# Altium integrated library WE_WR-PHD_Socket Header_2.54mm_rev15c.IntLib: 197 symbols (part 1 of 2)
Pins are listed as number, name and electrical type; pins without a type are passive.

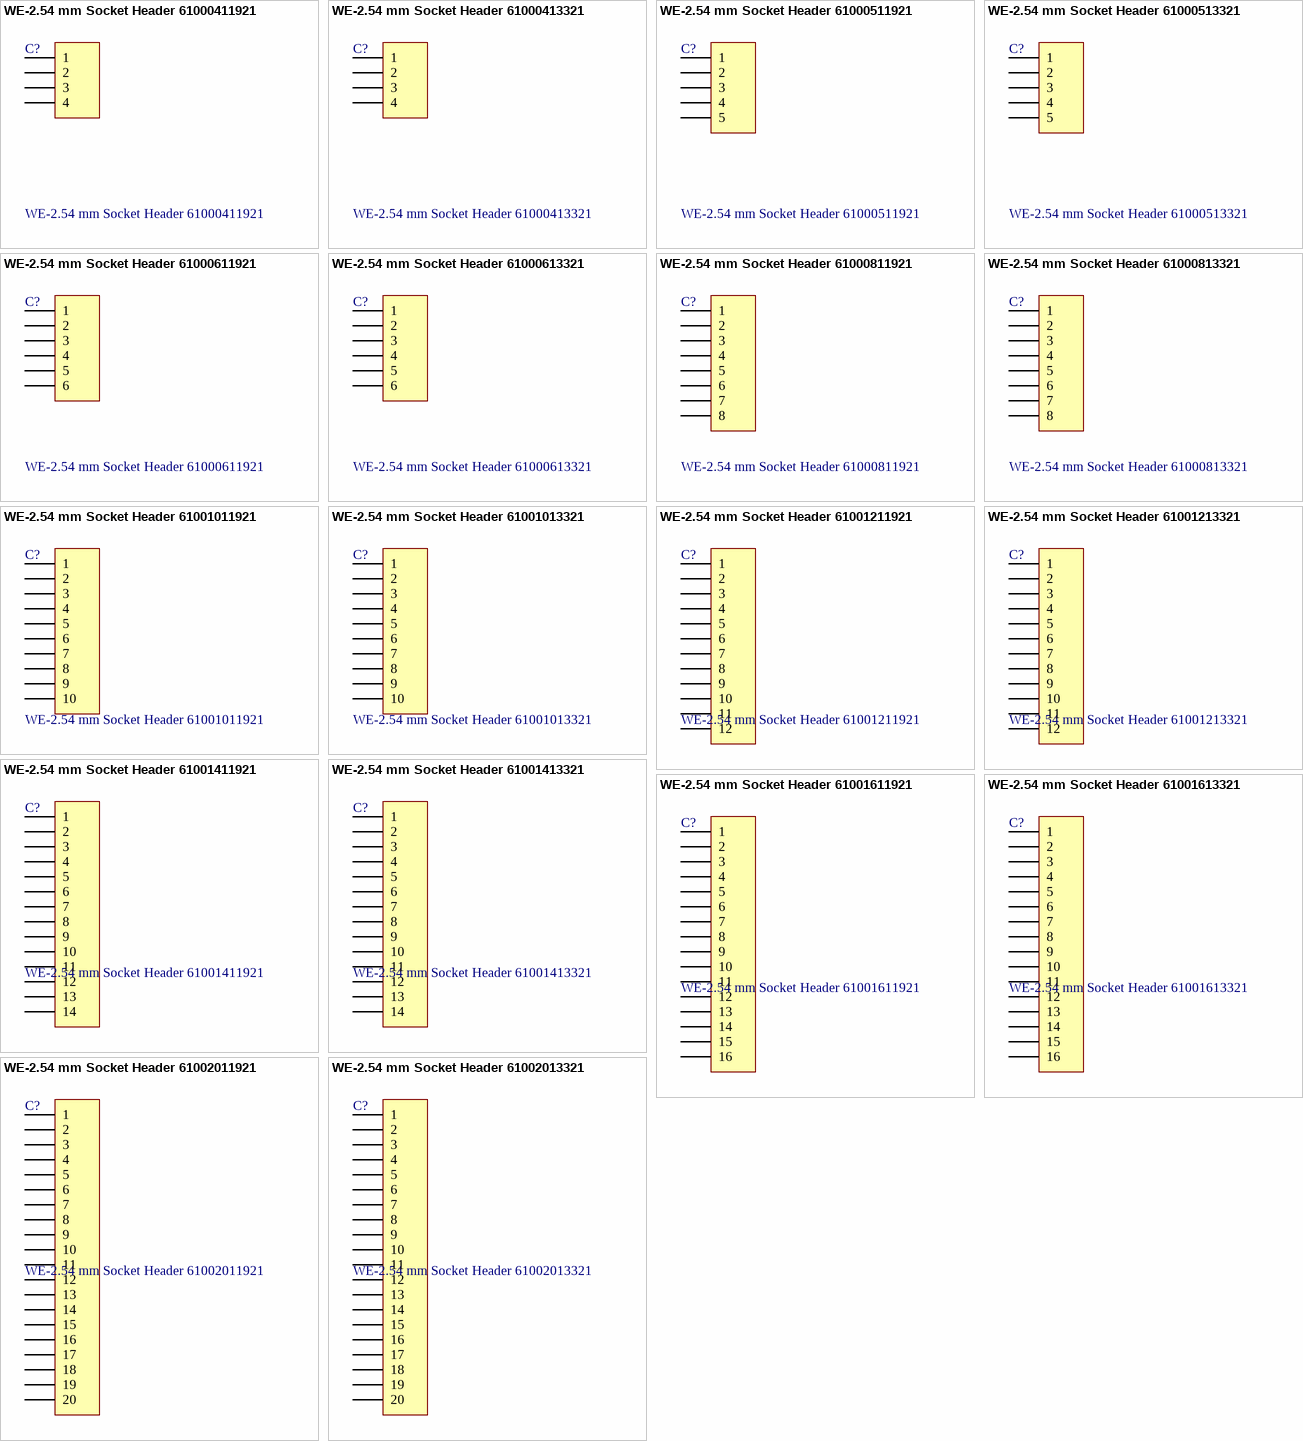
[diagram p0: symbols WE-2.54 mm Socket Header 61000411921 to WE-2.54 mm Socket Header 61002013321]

## WE-2.54 mm Socket Header 61000411921
designator C?
WR-PHD 2.54 mm SMT Socket Header; Manufacturer: Würth Elektronik eiSos GmbH; ComponentLink1 Description: Manufacturer; ComponentLink2 Description: Datasheet; NoPins: 4
footprint 61000411921 (4 pins, 1 row, straight, Type 1, gold plating)
pins: 1, 2, 3, 4

## WE-2.54 mm Socket Header 61000413321
designator C?
WR-PHD 2.54 mm SMT Socket Header; Manufacturer: Würth Elektronik eiSos GmbH; ComponentLink1 Description: Manufacturer; ComponentLink2 Description: Datasheet; NoPins: 4
footprint 61000413321 (4 pins, 1 row, straight, Type 2, gold plating)
pins: 1, 2, 3, 4

## WE-2.54 mm Socket Header 61000511921
designator C?
WR-PHD 2.54 mm SMT Socket Header; Manufacturer: Würth Elektronik eiSos GmbH; ComponentLink1 Description: Manufacturer; ComponentLink2 Description: Datasheet; NoPins: 5
footprint 61000511921 (5 pins, 1 row, straight, Type 1, gold plating)
pins: 1, 2, 3, 4, 5

## WE-2.54 mm Socket Header 61000513321
designator C?
WR-PHD 2.54 mm SMT Socket Header; Manufacturer: Würth Elektronik eiSos GmbH; ComponentLink1 Description: Manufacturer; ComponentLink2 Description: Datasheet; NoPins: 5
footprint 61000513321 (5 pins, 1 row, straight, Type 2, gold plating)
pins: 1, 2, 3, 4, 5

## WE-2.54 mm Socket Header 61000611921
designator C?
WR-PHD 2.54 mm SMT Socket Header; Manufacturer: Würth Elektronik eiSos GmbH; ComponentLink1 Description: Manufacturer; ComponentLink2 Description: Datasheet; NoPins: 6
footprint 61000611921 (6 pins, 1 row, straight, Type 1, gold plating)
pins: 1, 2, 3, 4, 5, 6

## WE-2.54 mm Socket Header 61000613321
designator C?
WR-PHD 2.54 mm SMT Socket Header; Manufacturer: Würth Elektronik eiSos GmbH; ComponentLink1 Description: Manufacturer; ComponentLink2 Description: Datasheet; NoPins: 6
footprint 61000613321 (6 pins, 1 row, straight, Type 2, gold plating)
pins: 1, 2, 3, 4, 5, 6

## WE-2.54 mm Socket Header 61000811921
designator C?
WR-PHD 2.54 mm SMT Socket Header; Manufacturer: Würth Elektronik eiSos GmbH; ComponentLink1 Description: Manufacturer; ComponentLink2 Description: Datasheet; NoPins: 8
footprint 61000811921 (8 pins, 1 row, straight, Type 1, gold plating)
pins: 1, 2, 3, 4, 5, 6, 7, 8

## WE-2.54 mm Socket Header 61000813321
designator C?
WR-PHD 2.54 mm SMT Socket Header; Manufacturer: Würth Elektronik eiSos GmbH; ComponentLink1 Description: Manufacturer; ComponentLink2 Description: Datasheet; NoPins: 8
footprint 61000813321 (8 pins, 1 row, straight, Type 2, gold plating)
pins: 1, 2, 3, 4, 5, 6, 7, 8

## WE-2.54 mm Socket Header 61001011921
designator C?
WR-PHD 2.54 mm SMT Socket Header; Manufacturer: Würth Elektronik eiSos GmbH; ComponentLink1 Description: Manufacturer; ComponentLink2 Description: Datasheet; NoPins: 10
footprint 61001011921 (10 pins, 1 row, straight, Type 1, gold plating)
pins: 1, 2, 3, 4, 5, 6, 7, 8, 9, 10

## WE-2.54 mm Socket Header 61001013321
designator C?
WR-PHD 2.54 mm SMT Socket Header; Manufacturer: Würth Elektronik eiSos GmbH; ComponentLink1 Description: Manufacturer; ComponentLink2 Description: Datasheet; NoPins: 10
footprint 61001013321 (10 pins, 1 row, straight, Type 2, gold plating)
pins: 1, 2, 3, 4, 5, 6, 7, 8, 9, 10

## WE-2.54 mm Socket Header 61001211921
designator C?
WR-PHD 2.54 mm SMT Socket Header; Manufacturer: Würth Elektronik eiSos GmbH; ComponentLink1 Description: Manufacturer; ComponentLink2 Description: Datasheet; NoPins: 12
footprint 61001211921 (12 pins, 1 row, straight, Type 1, gold plating)
pins: 1, 2, 3, 4, 5, 6, 7, 8, 9, 10, 11, 12

## WE-2.54 mm Socket Header 61001213321
designator C?
WR-PHD 2.54 mm SMT Socket Header; Manufacturer: Würth Elektronik eiSos GmbH; ComponentLink1 Description: Manufacturer; ComponentLink2 Description: Datasheet; NoPins: 12
footprint 61001213321 (12 pins, 1 row, straight, Type 2, gold plating)
pins: 1, 2, 3, 4, 5, 6, 7, 8, 9, 10, 11, 12

## WE-2.54 mm Socket Header 61001411921
designator C?
WR-PHD 2.54 mm SMT Socket Header; Manufacturer: Würth Elektronik eiSos GmbH; ComponentLink1 Description: Manufacturer; ComponentLink2 Description: Datasheet; NoPins: 14
footprint 61001411921 (14 pins, 1 row, straight, Type 1, gold plating)
pins: 1, 2, 3, 4, 5, 6, 7, 8, 9, 10, 11, 12, 13, 14

## WE-2.54 mm Socket Header 61001413321
designator C?
WR-PHD 2.54 mm SMT Socket Header; Manufacturer: Würth Elektronik eiSos GmbH; ComponentLink1 Description: Manufacturer; ComponentLink2 Description: Datasheet; NoPins: 14
footprint 61001413321 (14 pins, 1 row, straight, Type 2, gold plating)
pins: 1, 2, 3, 4, 5, 6, 7, 8, 9, 10, 11, 12, 13, 14

## WE-2.54 mm Socket Header 61001611921
designator C?
WR-PHD 2.54 mm SMT Socket Header; Manufacturer: Würth Elektronik eiSos GmbH; ComponentLink1 Description: Manufacturer; ComponentLink2 Description: Datasheet; NoPins: 16
footprint 61001611921 (16 pins, 1 row, straight, Type 1, gold plating)
pins: 1, 2, 3, 4, 5, 6, 7, 8, 9, 10, 11, 12, 13, 14, 15, 16

## WE-2.54 mm Socket Header 61001613321
designator C?
WR-PHD 2.54 mm SMT Socket Header; Manufacturer: Würth Elektronik eiSos GmbH; ComponentLink1 Description: Manufacturer; ComponentLink2 Description: Datasheet; NoPins: 16
footprint 61001613321 (16 pins, 1 row, straight, Type 2, gold plating)
pins: 1, 2, 3, 4, 5, 6, 7, 8, 9, 10, 11, 12, 13, 14, 15, 16

## WE-2.54 mm Socket Header 61002011921
designator C?
WR-PHD 2.54 mm SMT Socket Header; Manufacturer: Würth Elektronik eiSos GmbH; ComponentLink1 Description: Manufacturer; ComponentLink2 Description: Datasheet; NoPins: 20
footprint 61002011921 (20 pins, 1 row, straight, Type 1, gold plating)
pins: 1, 2, 3, 4, 5, 6, 7, 8, 9, 10, 11, 12, 13, 14, 15, 16, 17, 18, 19, 20

## WE-2.54 mm Socket Header 61002013321
designator C?
WR-PHD 2.54 mm SMT Socket Header; Manufacturer: Würth Elektronik eiSos GmbH; ComponentLink1 Description: Manufacturer; ComponentLink2 Description: Datasheet; NoPins: 20
footprint 61002013321 (20 pins, 1 row, straight, Type 2, gold plating)
pins: 1, 2, 3, 4, 5, 6, 7, 8, 9, 10, 11, 12, 13, 14, 15, 16, 17, 18, 19, 20


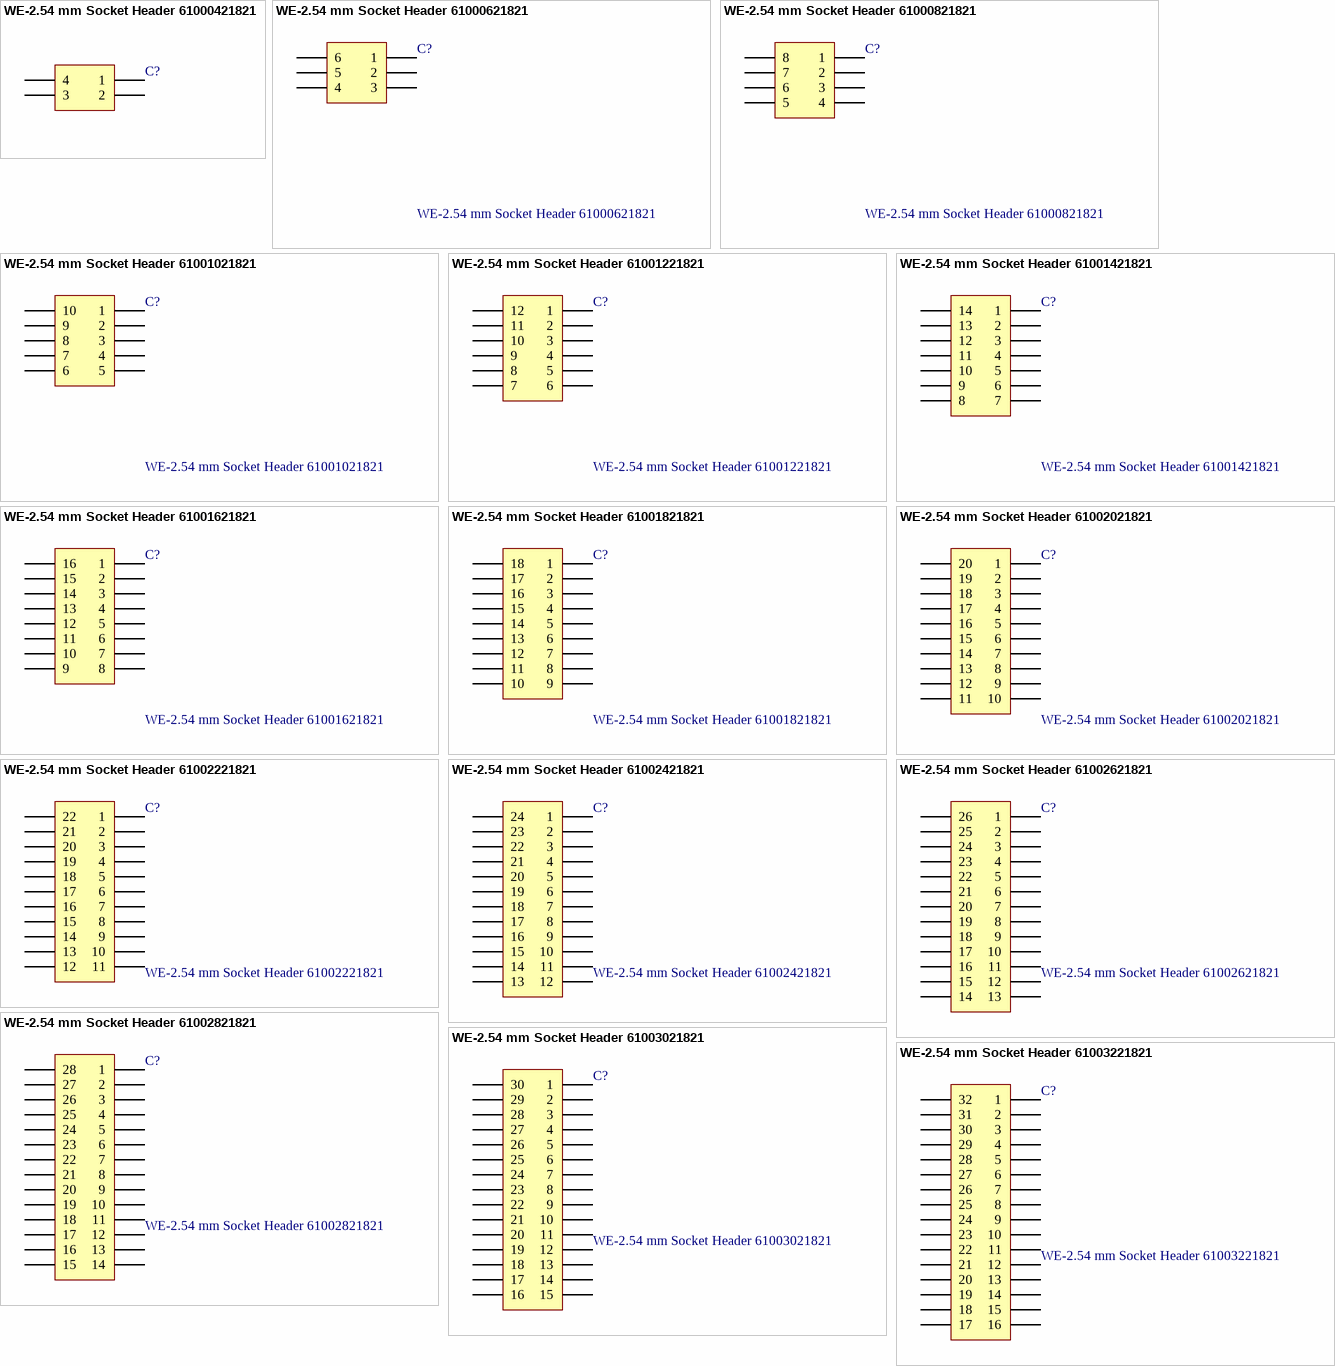
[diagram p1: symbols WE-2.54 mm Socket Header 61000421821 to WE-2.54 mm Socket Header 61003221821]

## WE-2.54 mm Socket Header 61000421821
designator C?
WR-PHD 2.54 mm Dual SMT Socket Header; Manufacturer: Würth Elektronik eiSos GmbH; ComponentLink1 Description: Manufacturer; ComponentLink2 Description: Datasheet; NoPins: 04
footprint 61000421821 (4 pins, dual row, straight, gold plating)
pins: 1, 2, 3, 4

## WE-2.54 mm Socket Header 61000621821
designator C?
WR-PHD 2.54 mm Dual SMT Socket Header; Manufacturer: Würth Elektronik eiSos GmbH; ComponentLink1 Description: Manufacturer; ComponentLink2 Description: Datasheet; NoPins: 06
footprint 61000621821 (6 pins, dual row, straight, gold plating)
pins: 1, 2, 3, 4, 5, 6

## WE-2.54 mm Socket Header 61000821821
designator C?
WR-PHD 2.54 mm Dual SMT Socket Header; Manufacturer: Würth Elektronik eiSos GmbH; ComponentLink1 Description: Manufacturer; ComponentLink2 Description: Datasheet; NoPins: 08
footprint 61000821821 (8 pins, dual row, straight, gold plating)
pins: 1, 2, 3, 4, 5, 6, 7, 8

## WE-2.54 mm Socket Header 61001021821
designator C?
WR-PHD 2.54 mm Dual SMT Socket Header; Manufacturer: Würth Elektronik eiSos GmbH; ComponentLink1 Description: Manufacturer; ComponentLink2 Description: Datasheet; NoPins: 10
footprint 61001021821 (10 pins, dual row, straight, gold plating)
pins: 1, 2, 3, 4, 5, 6, 7, 8, 9, 10

## WE-2.54 mm Socket Header 61001221821
designator C?
WR-PHD 2.54 mm Dual SMT Socket Header; Manufacturer: Würth Elektronik eiSos GmbH; ComponentLink1 Description: Manufacturer; ComponentLink2 Description: Datasheet; NoPins: 12
footprint 61001221821 (12 pins, dual row, straight, gold plating)
pins: 1, 2, 3, 4, 5, 6, 7, 8, 9, 10, 11, 12

## WE-2.54 mm Socket Header 61001421821
designator C?
WR-PHD 2.54 mm Dual SMT Socket Header; Manufacturer: Würth Elektronik eiSos GmbH; ComponentLink1 Description: Manufacturer; ComponentLink2 Description: Datasheet; NoPins: 14
footprint 61001421821 (14 pins, dual row, straight, gold plating)
pins: 1, 2, 3, 4, 5, 6, 7, 8, 9, 10, 11, 12, 13, 14

## WE-2.54 mm Socket Header 61001621821
designator C?
WR-PHD 2.54 mm Dual SMT Socket Header; Manufacturer: Würth Elektronik eiSos GmbH; ComponentLink1 Description: Manufacturer; ComponentLink2 Description: Datasheet; NoPins: 16
footprint 61001621821 (16 pins, dual row, straight, gold plating)
pins: 1, 2, 3, 4, 5, 6, 7, 8, 9, 10, 11, 12, 13, 14, 15, 16

## WE-2.54 mm Socket Header 61001821821
designator C?
WR-PHD 2.54 mm Dual SMT Socket Header; Manufacturer: Würth Elektronik eiSos GmbH; ComponentLink1 Description: Manufacturer; ComponentLink2 Description: Datasheet; NoPins: 18
footprint 61001821821 (18 pins, dual row, straight, gold plating)
pins: 1, 2, 3, 4, 5, 6, 7, 8, 9, 10, 11, 12, 13, 14, 15, 16, 17, 18

## WE-2.54 mm Socket Header 61002021821
designator C?
WR-PHD 2.54 mm Dual SMT Socket Header; Manufacturer: Würth Elektronik eiSos GmbH; ComponentLink1 Description: Manufacturer; ComponentLink2 Description: Datasheet; NoPins: 20
footprint 61002021821 (20 pins, dual row, straight, gold plating)
pins: 1, 2, 3, 4, 5, 6, 7, 8, 9, 10, 11, 12, 13, 14, 15, 16, 17, 18, 19, 20

## WE-2.54 mm Socket Header 61002221821
designator C?
WR-PHD 2.54 mm Dual SMT Socket Header; Manufacturer: Würth Elektronik eiSos GmbH; ComponentLink1 Description: Manufacturer; ComponentLink2 Description: Datasheet; NoPins: 22
footprint 61002221821 (22 pins, dual row, straight, gold plating)
pins: 1, 2, 3, 4, 5, 6, 7, 8, 9, 10, 11, 12, 13, 14, 15, 16, 17, 18, 19, 20, 21, 22

## WE-2.54 mm Socket Header 61002421821
designator C?
WR-PHD 2.54 mm Dual SMT Socket Header; Manufacturer: Würth Elektronik eiSos GmbH; ComponentLink1 Description: Manufacturer; ComponentLink2 Description: Datasheet; NoPins: 24
footprint 61002421821 (24 pins, dual row, straight, gold plating)
pins: 1, 2, 3, 4, 5, 6, 7, 8, 9, 10, 11, 12, 13, 14, 15, 16, 17, 18, 19, 20, 21, 22, 23, 24

## WE-2.54 mm Socket Header 61002621821
designator C?
WR-PHD 2.54 mm Dual SMT Socket Header; Manufacturer: Würth Elektronik eiSos GmbH; ComponentLink1 Description: Manufacturer; ComponentLink2 Description: Datasheet; NoPins: 26
footprint 61002621821 (26 pins, dual row, straight, gold plating)
pins: 1, 2, 3, 4, 5, 6, 7, 8, 9, 10, 11, 12, 13, 14, 15, 16, 17, 18, 19, 20, 21, 22, 23, 24, 25, 26

## WE-2.54 mm Socket Header 61002821821
designator C?
WR-PHD 2.54 mm Dual SMT Socket Header; Manufacturer: Würth Elektronik eiSos GmbH; ComponentLink1 Description: Manufacturer; ComponentLink2 Description: Datasheet; NoPins: 28
footprint 61002821821 (28 pins, dual row, straight, gold plating)
pins: 1, 2, 3, 4, 5, 6, 7, 8, 9, 10, 11, 12, 13, 14, 15, 16, 17, 18, 19, 20, 21, 22, 23, 24, 25, 26, 27, 28

## WE-2.54 mm Socket Header 61003021821
designator C?
WR-PHD 2.54 mm Dual SMT Socket Header; Manufacturer: Würth Elektronik eiSos GmbH; ComponentLink1 Description: Manufacturer; ComponentLink2 Description: Datasheet; NoPins: 30
footprint 61003021821 (30 pins, dual row, straight, gold plating)
pins: 1, 2, 3, 4, 5, 6, 7, 8, 9, 10, 11, 12, 13, 14, 15, 16, 17, 18, 19, 20, 21, 22, 23, 24, 25, 26, 27, 28, 29, 30

## WE-2.54 mm Socket Header 61003221821
designator C?
WR-PHD 2.54 mm Dual SMT Socket Header; Manufacturer: Würth Elektronik eiSos GmbH; ComponentLink1 Description: Manufacturer; ComponentLink2 Description: Datasheet; NoPins: 32
footprint 61003221821 (32 pins, dual row, straight, gold plating)
pins: 1, 2, 3, 4, 5, 6, 7, 8, 9, 10, 11, 12, 13, 14, 15, 16, 17, 18, 19, 20, 21, 22, 23, 24, 25, 26, 27, 28, 29, 30, 31, 32

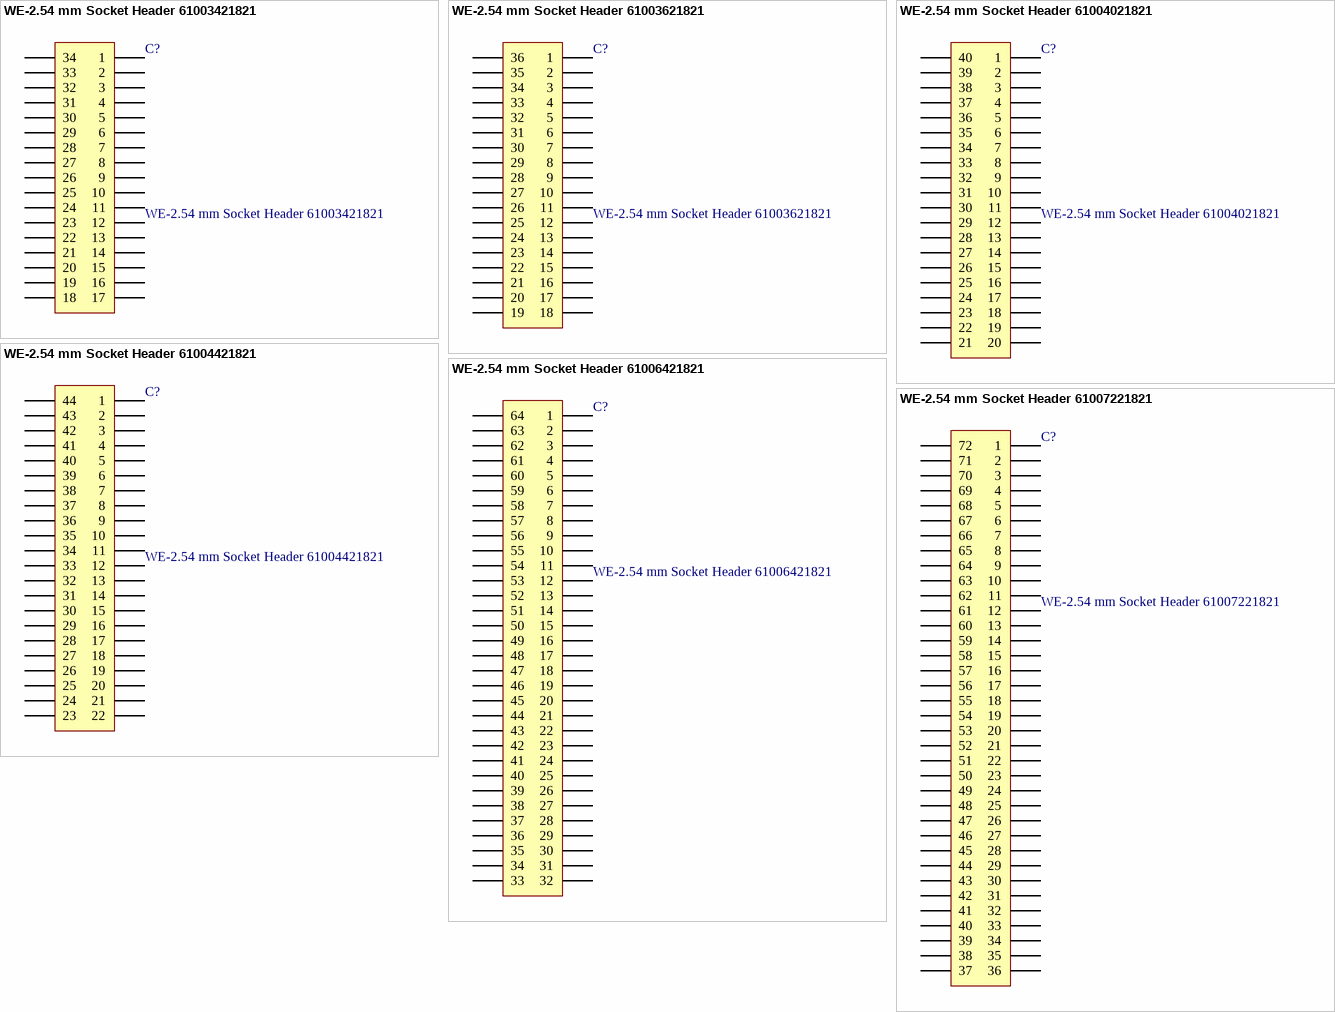
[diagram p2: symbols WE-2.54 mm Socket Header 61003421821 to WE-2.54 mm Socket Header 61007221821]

## WE-2.54 mm Socket Header 61003421821
designator C?
WR-PHD 2.54 mm Dual SMT Socket Header; Manufacturer: Würth Elektronik eiSos GmbH; ComponentLink1 Description: Manufacturer; ComponentLink2 Description: Datasheet; NoPins: 34
footprint 61003421821 (34 pins, dual row, straight, gold plating)
pins: 1, 2, 3, 4, 5, 6, 7, 8, 9, 10, 11, 12, 13, 14, 15, 16, 17, 18, 19, 20, 21, 22, 23, 24, 25, 26, 27, 28, 29, 30, 31, 32, 33, 34

## WE-2.54 mm Socket Header 61003621821
designator C?
WR-PHD 2.54 mm Dual SMT Socket Header; Manufacturer: Würth Elektronik eiSos GmbH; ComponentLink1 Description: Manufacturer; ComponentLink2 Description: Datasheet; NoPins: 36
footprint 61003621821 (36 pins, dual row, straight, gold plating)
pins: 1, 2, 3, 4, 5, 6, 7, 8, 9, 10, 11, 12, 13, 14, 15, 16, 17, 18, 19, 20, 21, 22, 23, 24, 25, 26, 27, 28, 29, 30, 31, 32, 33, 34, 35, 36

## WE-2.54 mm Socket Header 61004021821
designator C?
WR-PHD 2.54 mm Dual SMT Socket Header; Manufacturer: Würth Elektronik eiSos GmbH; ComponentLink1 Description: Manufacturer; ComponentLink2 Description: Datasheet; NoPins: 40
footprint 61004021821 (40 pins, dual row, straight, gold plating)
pins: 1, 2, 3, 4, 5, 6, 7, 8, 9, 10, 11, 12, 13, 14, 15, 16, 17, 18, 19, 20, 21, 22, 23, 24, 25, 26, 27, 28, 29, 30, 31, 32, 33, 34, 35, 36, 37, 38, 39, 40

## WE-2.54 mm Socket Header 61004421821
designator C?
WR-PHD 2.54 mm Dual SMT Socket Header; Manufacturer: Würth Elektronik eiSos GmbH; ComponentLink1 Description: Manufacturer; ComponentLink2 Description: Datasheet; NoPins: 44
footprint 61004421821 (44 pins, dual row, straight, gold plating)
pins: 1, 2, 3, 4, 5, 6, 7, 8, 9, 10, 11, 12, 13, 14, 15, 16, 17, 18, 19, 20, 21, 22, 23, 24, 25, 26, 27, 28, 29, 30, 31, 32, 33, 34, 35, 36, 37, 38, 39, 40, 41, 42, 43, 44

## WE-2.54 mm Socket Header 61006421821
designator C?
WR-PHD 2.54 mm Dual SMT Socket Header; Manufacturer: Würth Elektronik eiSos GmbH; ComponentLink1 Description: Manufacturer; ComponentLink2 Description: Datasheet; NoPins: 64
footprint 61006421821 (64 pins, dual row, straight, gold plating)
pins: 1, 2, 3, 4, 5, 6, 7, 8, 9, 10, 11, 12, 13, 14, 15, 16, 17, 18, 19, 20, 21, 22, 23, 24, 25, 26, 27, 28, 29, 30, 31, 32, 33, 34, 35, 36, 37, 38, 39, 40, 41, 42, 43, 44, 45, 46, 47, 48, 49, 50, 51, 52, 53, 54, 55, 56, 57, 58, 59, 60, 61, 62, 63, 64

## WE-2.54 mm Socket Header 61007221821
designator C?
WR-PHD 2.54 mm Dual SMT Socket Header; Manufacturer: Würth Elektronik eiSos GmbH; ComponentLink1 Description: Manufacturer; ComponentLink2 Description: Datasheet; NoPins: 72
footprint 61007221821 (72 pins, dual row, straight, gold plating)
pins: 1, 2, 3, 4, 5, 6, 7, 8, 9, 10, 11, 12, 13, 14, 15, 16, 17, 18, 19, 20, 21, 22, 23, 24, 25, 26, 27, 28, 29, 30, 31, 32, 33, 34, 35, 36, 37, 38, 39, 40, 41, 42, 43, 44, 45, 46, 47, 48, 49, 50, 51, 52, 53, 54, 55, 56, 57, 58, 59, 60, 61, 62, 63, 64, 65, 66, 67, 68, 69, 70, 71, 72


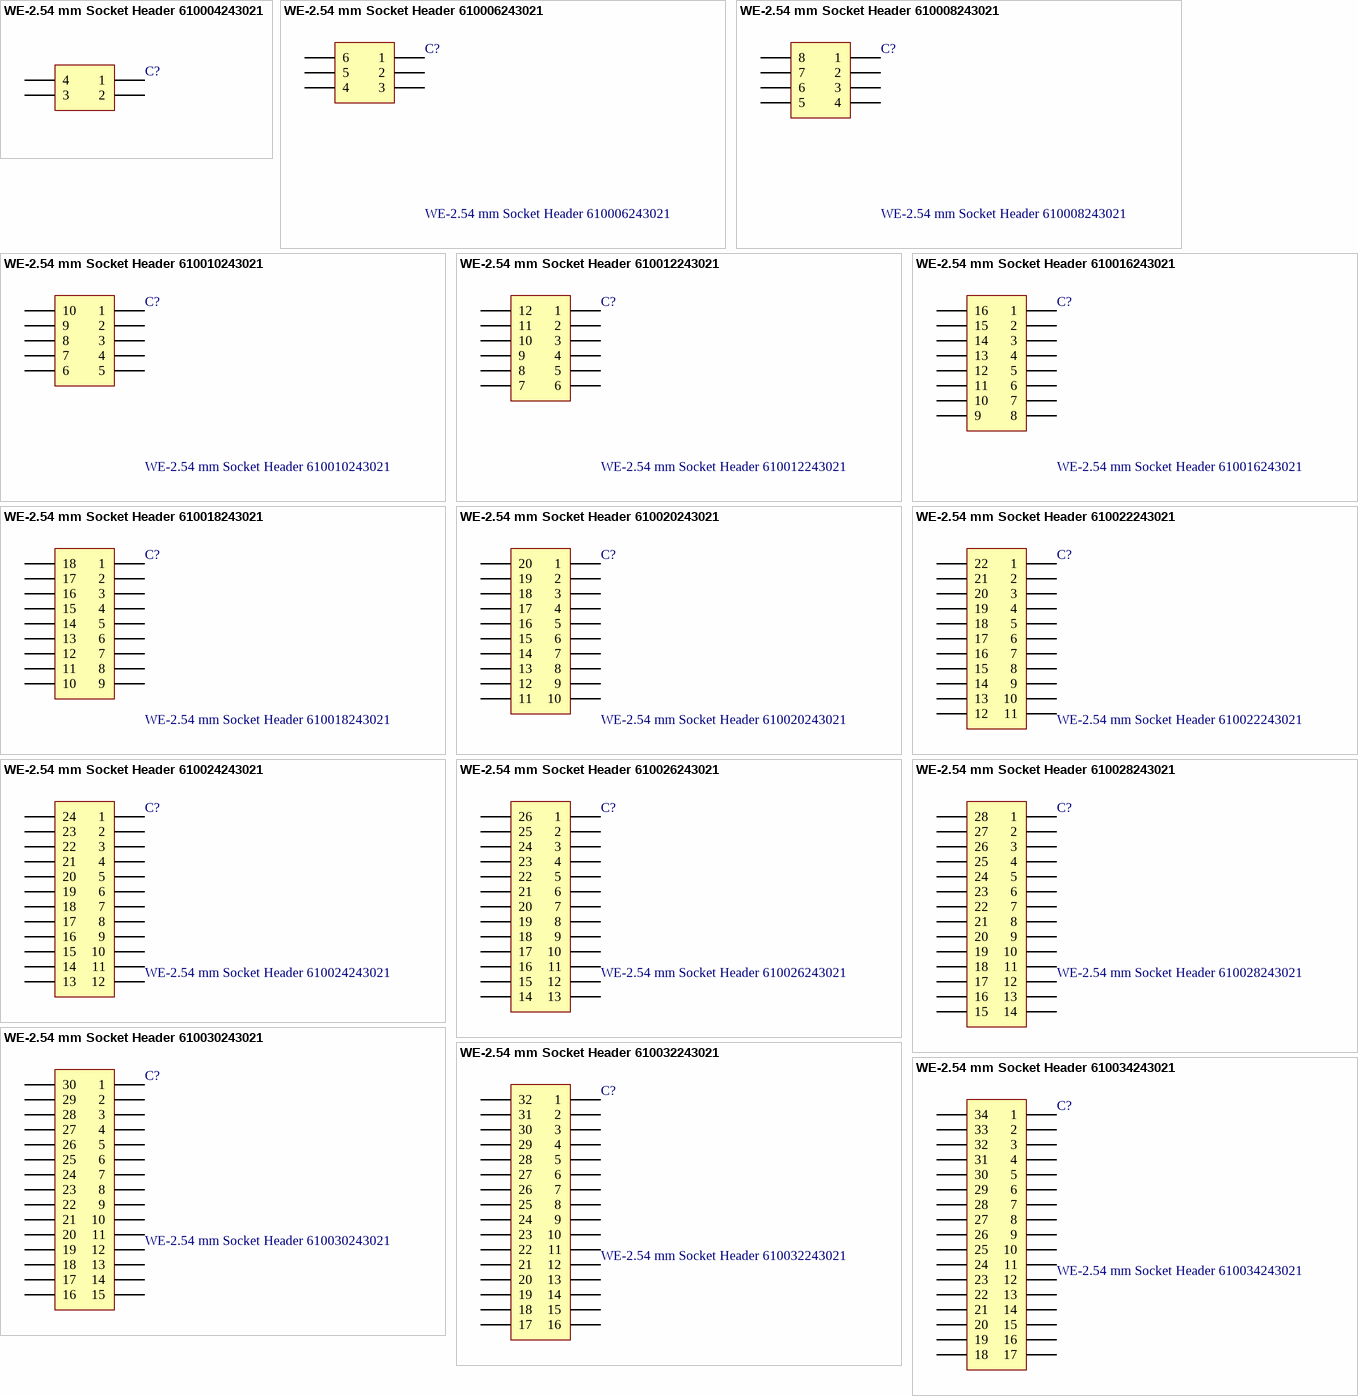
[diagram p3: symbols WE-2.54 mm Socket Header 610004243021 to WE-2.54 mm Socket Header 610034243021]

## WE-2.54 mm Socket Header 610004243021
designator C?
WR-PHD 2.54 mm SMT Dual Socket Header Bottom Entry; Manufacturer: Würth Elektronik eiSos GmbH; ComponentLink1 Description: Manufacturer; ComponentLink2 Description: Datasheet; NoPins: 04
footprint 610004243021 (04p dual row straight 3,7mm height)
pins: 1, 2, 3, 4

## WE-2.54 mm Socket Header 610006243021
designator C?
WR-PHD 2.54 mm SMT Dual Socket Header Bottom Entry; Manufacturer: Würth Elektronik eiSos GmbH; ComponentLink1 Description: Manufacturer; ComponentLink2 Description: Datasheet; NoPins: 06
footprint 610006243021 (06p dual row straight 3,7mm height)
pins: 1, 2, 3, 4, 5, 6

## WE-2.54 mm Socket Header 610008243021
designator C?
WR-PHD 2.54 mm SMT Dual Socket Header Bottom Entry; Manufacturer: Würth Elektronik eiSos GmbH; ComponentLink1 Description: Manufacturer; ComponentLink2 Description: Datasheet; NoPins: 08
footprint 610008243021 (08p dual row straight 3,7mm height)
pins: 1, 2, 3, 4, 5, 6, 7, 8

## WE-2.54 mm Socket Header 610010243021
designator C?
WR-PHD 2.54 mm SMT Dual Socket Header Bottom Entry; Manufacturer: Würth Elektronik eiSos GmbH; ComponentLink1 Description: Manufacturer; ComponentLink2 Description: Datasheet; NoPins: 10
footprint 610010243021 (10p dual row straight 3,7mm height)
pins: 1, 2, 3, 4, 5, 6, 7, 8, 9, 10

## WE-2.54 mm Socket Header 610012243021
designator C?
WR-PHD 2.54 mm SMT Dual Socket Header Bottom Entry; Manufacturer: Würth Elektronik eiSos GmbH; ComponentLink1 Description: Manufacturer; ComponentLink2 Description: Datasheet; NoPins: 12
footprint 610012243021 (12p dual row straight 3,7mm height)
pins: 1, 2, 3, 4, 5, 6, 7, 8, 9, 10, 11, 12

## WE-2.54 mm Socket Header 610016243021
designator C?
WR-PHD 2.54 mm SMT Dual Socket Header Bottom Entry; Manufacturer: Würth Elektronik eiSos GmbH; ComponentLink1 Description: Manufacturer; ComponentLink2 Description: Datasheet; NoPins: 16
footprint 610016243021 (16p dual row straight 3,7mm height)
pins: 1, 2, 3, 4, 5, 6, 7, 8, 9, 10, 11, 12, 13, 14, 15, 16

## WE-2.54 mm Socket Header 610018243021
designator C?
WR-PHD 2.54 mm SMT Dual Socket Header Bottom Entry; Manufacturer: Würth Elektronik eiSos GmbH; ComponentLink1 Description: Manufacturer; ComponentLink2 Description: Datasheet; NoPins: 18
footprint 610018243021 (18p dual row straight 3,7mm height)
pins: 1, 2, 3, 4, 5, 6, 7, 8, 9, 10, 11, 12, 13, 14, 15, 16, 17, 18

## WE-2.54 mm Socket Header 610020243021
designator C?
WR-PHD 2.54 mm SMT Dual Socket Header Bottom Entry; Manufacturer: Würth Elektronik eiSos GmbH; ComponentLink1 Description: Manufacturer; ComponentLink2 Description: Datasheet; NoPins: 20
footprint 610020243021 (20p dual row straight 3,7mm height)
pins: 1, 2, 3, 4, 5, 6, 7, 8, 9, 10, 11, 12, 13, 14, 15, 16, 17, 18, 19, 20

## WE-2.54 mm Socket Header 610022243021
designator C?
WR-PHD 2.54 mm SMT Dual Socket Header Bottom Entry; Manufacturer: Würth Elektronik eiSos GmbH; ComponentLink1 Description: Manufacturer; ComponentLink2 Description: Datasheet; NoPins: 22
footprint 610022243021 (22p dual row straight 3,7mm height)
pins: 1, 2, 3, 4, 5, 6, 7, 8, 9, 10, 11, 12, 13, 14, 15, 16, 17, 18, 19, 20, 21, 22

## WE-2.54 mm Socket Header 610024243021
designator C?
WR-PHD 2.54 mm SMT Dual Socket Header Bottom Entry; Manufacturer: Würth Elektronik eiSos GmbH; ComponentLink1 Description: Manufacturer; ComponentLink2 Description: Datasheet; NoPins: 24
footprint 610024243021 (24p dual row straight 3,7mm height)
pins: 1, 2, 3, 4, 5, 6, 7, 8, 9, 10, 11, 12, 13, 14, 15, 16, 17, 18, 19, 20, 21, 22, 23, 24

## WE-2.54 mm Socket Header 610026243021
designator C?
WR-PHD 2.54 mm SMT Dual Socket Header Bottom Entry; Manufacturer: Würth Elektronik eiSos GmbH; ComponentLink1 Description: Manufacturer; ComponentLink2 Description: Datasheet; NoPins: 26
footprint 610026243021 (26p dual row straight 3,7mm height)
pins: 1, 2, 3, 4, 5, 6, 7, 8, 9, 10, 11, 12, 13, 14, 15, 16, 17, 18, 19, 20, 21, 22, 23, 24, 25, 26

## WE-2.54 mm Socket Header 610028243021
designator C?
WR-PHD 2.54 mm SMT Dual Socket Header Bottom Entry; Manufacturer: Würth Elektronik eiSos GmbH; ComponentLink1 Description: Manufacturer; ComponentLink2 Description: Datasheet; NoPins: 28
footprint 610028243021 (28p dual row straight 3,7mm height)
pins: 1, 2, 3, 4, 5, 6, 7, 8, 9, 10, 11, 12, 13, 14, 15, 16, 17, 18, 19, 20, 21, 22, 23, 24, 25, 26, 27, 28

## WE-2.54 mm Socket Header 610030243021
designator C?
WR-PHD 2.54 mm SMT Dual Socket Header Bottom Entry; Manufacturer: Würth Elektronik eiSos GmbH; ComponentLink1 Description: Manufacturer; ComponentLink2 Description: Datasheet; NoPins: 30
footprint 610030243021 (30p dual row straight 3,7mm height)
pins: 1, 2, 3, 4, 5, 6, 7, 8, 9, 10, 11, 12, 13, 14, 15, 16, 17, 18, 19, 20, 21, 22, 23, 24, 25, 26, 27, 28, 29, 30

## WE-2.54 mm Socket Header 610032243021
designator C?
WR-PHD 2.54 mm SMT Dual Socket Header Bottom Entry; Manufacturer: Würth Elektronik eiSos GmbH; ComponentLink1 Description: Manufacturer; ComponentLink2 Description: Datasheet; NoPins: 32
footprint 610032243021 (32p dual row straight 3,7mm height)
pins: 1, 2, 3, 4, 5, 6, 7, 8, 9, 10, 11, 12, 13, 14, 15, 16, 17, 18, 19, 20, 21, 22, 23, 24, 25, 26, 27, 28, 29, 30, 31, 32

## WE-2.54 mm Socket Header 610034243021
designator C?
WR-PHD 2.54 mm SMT Dual Socket Header Bottom Entry; Manufacturer: Würth Elektronik eiSos GmbH; ComponentLink1 Description: Manufacturer; ComponentLink2 Description: Datasheet; NoPins: 34
footprint 610034243021 (34p dual row straight 3,7mm height)
pins: 1, 2, 3, 4, 5, 6, 7, 8, 9, 10, 11, 12, 13, 14, 15, 16, 17, 18, 19, 20, 21, 22, 23, 24, 25, 26, 27, 28, 29, 30, 31, 32, 33, 34

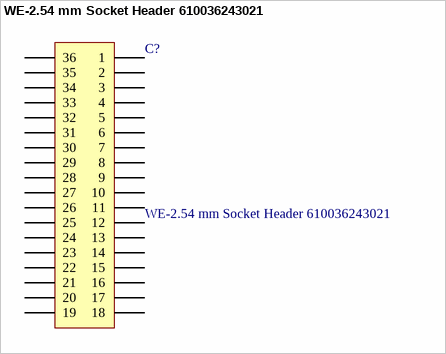
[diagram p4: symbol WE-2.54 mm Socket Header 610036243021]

## WE-2.54 mm Socket Header 610036243021
designator C?
WR-PHD 2.54 mm SMT Dual Socket Header Bottom Entry; Manufacturer: Würth Elektronik eiSos GmbH; ComponentLink1 Description: Manufacturer; ComponentLink2 Description: Datasheet; NoPins: 36
footprint 610036243021 (36p dual row straight 3,7mm height)
pins: 1, 2, 3, 4, 5, 6, 7, 8, 9, 10, 11, 12, 13, 14, 15, 16, 17, 18, 19, 20, 21, 22, 23, 24, 25, 26, 27, 28, 29, 30, 31, 32, 33, 34, 35, 36


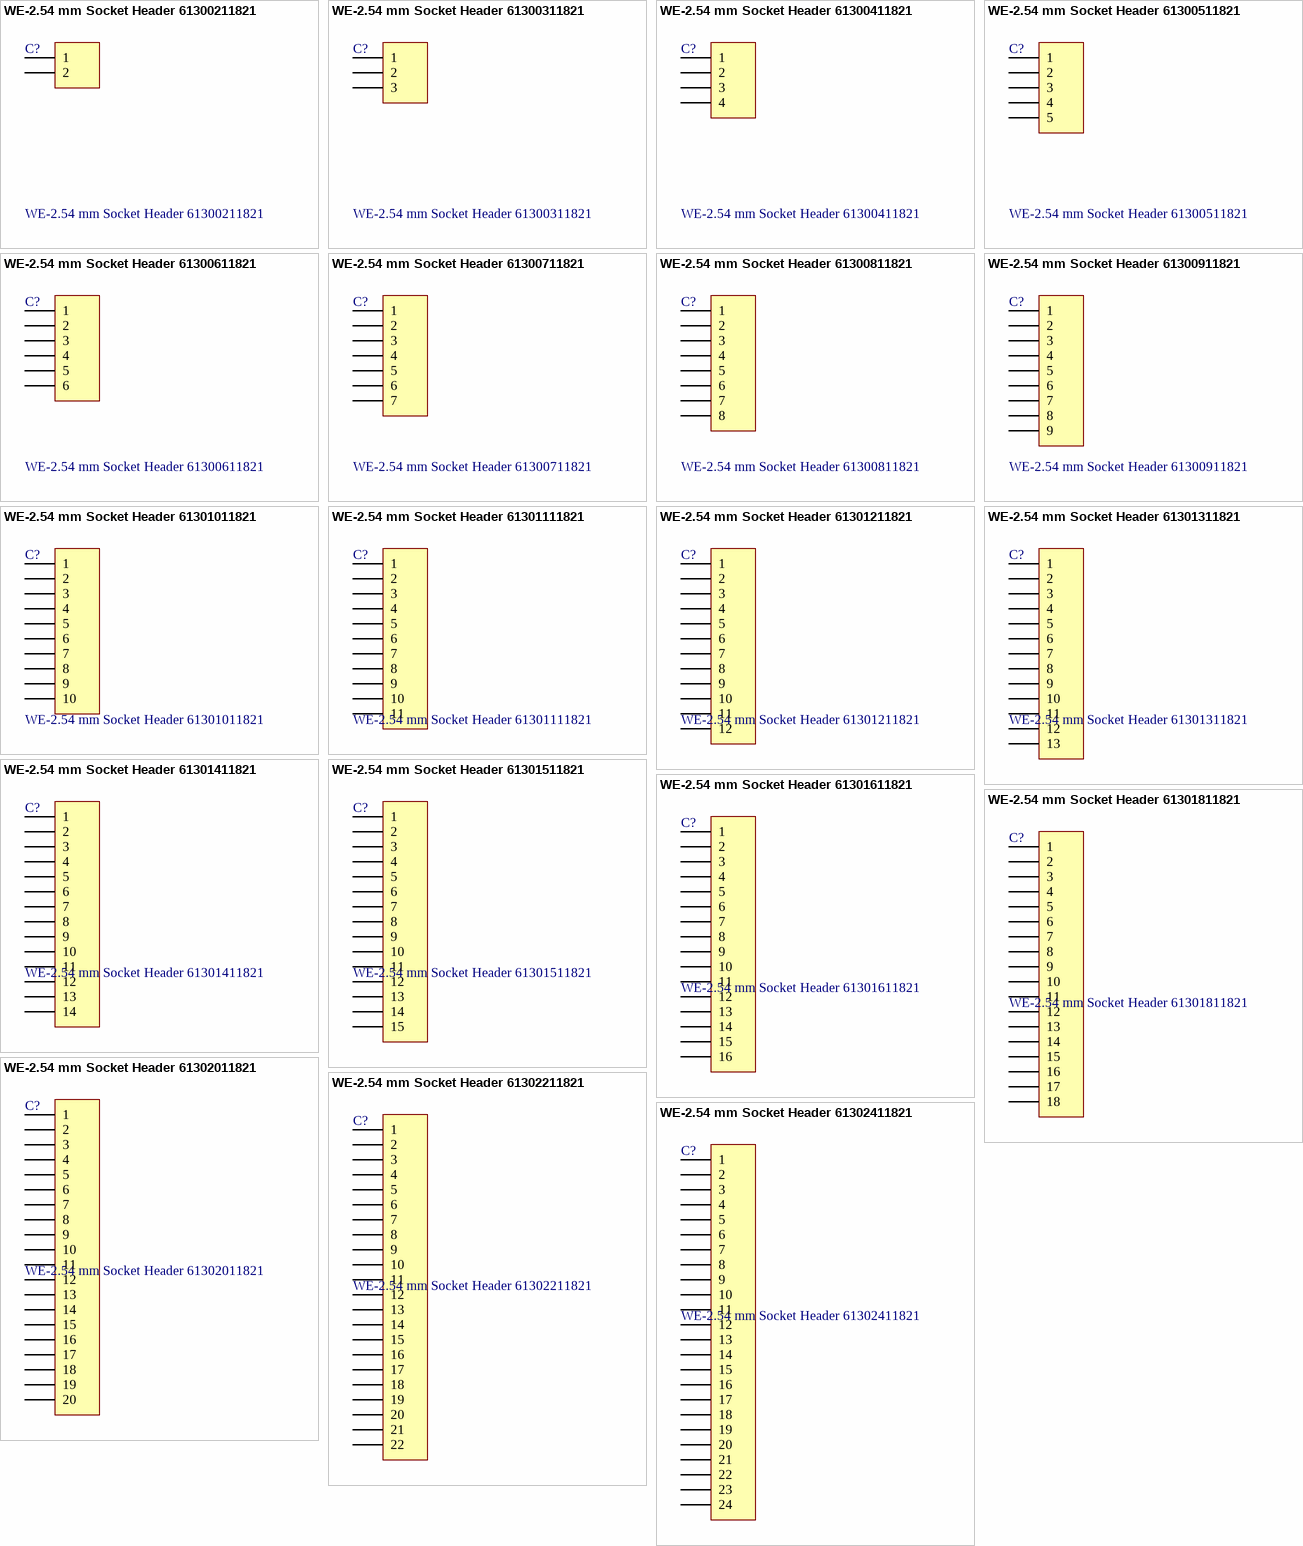
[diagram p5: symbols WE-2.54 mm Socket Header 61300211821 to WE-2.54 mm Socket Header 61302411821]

## WE-2.54 mm Socket Header 61300211821
designator C?
WR-PHD 2.54 mm Socket Header; Manufacturer: Würth Elektronik eiSos GmbH; ComponentLink1 Description: Manufacturer; ComponentLink2 Description: Datasheet; NoPins: 02
footprint 61300211821 (2 row, straight, gold plating)
pins: 1, 2

## WE-2.54 mm Socket Header 61300311821
designator C?
WR-PHD 2.54 mm Socket Header; Manufacturer: Würth Elektronik eiSos GmbH; ComponentLink1 Description: Manufacturer; ComponentLink2 Description: Datasheet; NoPins: 03
footprint 61300311821 (3 row, straight, gold plating)
pins: 1, 2, 3

## WE-2.54 mm Socket Header 61300411821
designator C?
WR-PHD 2.54 mm Socket Header; Manufacturer: Würth Elektronik eiSos GmbH; ComponentLink1 Description: Manufacturer; ComponentLink2 Description: Datasheet; NoPins: 04
footprint 61300411821 (4 row, straight, gold plating)
pins: 1, 2, 3, 4

## WE-2.54 mm Socket Header 61300511821
designator C?
WR-PHD 2.54 mm Socket Header; Manufacturer: Würth Elektronik eiSos GmbH; ComponentLink1 Description: Manufacturer; ComponentLink2 Description: Datasheet; NoPins: 05
footprint 61300511821 (5 row, straight, gold plating)
pins: 1, 2, 3, 4, 5

## WE-2.54 mm Socket Header 61300611821
designator C?
WR-PHD 2.54 mm Socket Header; Manufacturer: Würth Elektronik eiSos GmbH; ComponentLink1 Description: Manufacturer; ComponentLink2 Description: Datasheet; NoPins: 06
footprint 61300611821 (6 row, straight, gold plating)
pins: 1, 2, 3, 4, 5, 6

## WE-2.54 mm Socket Header 61300711821
designator C?
WR-PHD 2.54 mm Socket Header; Manufacturer: Würth Elektronik eiSos GmbH; ComponentLink1 Description: Manufacturer; ComponentLink2 Description: Datasheet; NoPins: 07
footprint 61300711821 (7 row, straight, gold plating)
pins: 1, 2, 3, 4, 5, 6, 7

## WE-2.54 mm Socket Header 61300811821
designator C?
WR-PHD 2.54 mm Socket Header; Manufacturer: Würth Elektronik eiSos GmbH; ComponentLink1 Description: Manufacturer; ComponentLink2 Description: Datasheet; NoPins: 08
footprint 61300811821 (8 row, straight, gold plating)
pins: 1, 2, 3, 4, 5, 6, 7, 8

## WE-2.54 mm Socket Header 61300911821
designator C?
WR-PHD 2.54 mm Socket Header; Manufacturer: Würth Elektronik eiSos GmbH; ComponentLink1 Description: Manufacturer; ComponentLink2 Description: Datasheet; NoPins: 09
footprint 61300911821 (9 row, straight, gold plating)
pins: 1, 2, 3, 4, 5, 6, 7, 8, 9

## WE-2.54 mm Socket Header 61301011821
designator C?
WR-PHD 2.54 mm Socket Header; Manufacturer: Würth Elektronik eiSos GmbH; ComponentLink1 Description: Manufacturer; ComponentLink2 Description: Datasheet; NoPins: 10
footprint 61301011821 (10 row, straight, gold plating)
pins: 1, 2, 3, 4, 5, 6, 7, 8, 9, 10

## WE-2.54 mm Socket Header 61301111821
designator C?
WR-PHD 2.54 mm Socket Header; Manufacturer: Würth Elektronik eiSos GmbH; ComponentLink1 Description: Manufacturer; ComponentLink2 Description: Datasheet; NoPins: 11
footprint 61301111821 (11 row, straight, gold plating)
pins: 1, 2, 3, 4, 5, 6, 7, 8, 9, 10, 11

## WE-2.54 mm Socket Header 61301211821
designator C?
WR-PHD 2.54 mm Socket Header; Manufacturer: Würth Elektronik eiSos GmbH; ComponentLink1 Description: Manufacturer; ComponentLink2 Description: Datasheet; NoPins: 12
footprint 61301211821 (12 row, straight, gold plating)
pins: 1, 2, 3, 4, 5, 6, 7, 8, 9, 10, 11, 12

## WE-2.54 mm Socket Header 61301311821
designator C?
WR-PHD 2.54 mm Socket Header; Manufacturer: Würth Elektronik eiSos GmbH; ComponentLink1 Description: Manufacturer; ComponentLink2 Description: Datasheet; NoPins: 13
footprint 61301311821 (13 row, straight, gold plating)
pins: 1, 2, 3, 4, 5, 6, 7, 8, 9, 10, 11, 12, 13

## WE-2.54 mm Socket Header 61301411821
designator C?
WR-PHD 2.54 mm Socket Header; Manufacturer: Würth Elektronik eiSos GmbH; ComponentLink1 Description: Manufacturer; ComponentLink2 Description: Datasheet; NoPins: 14
footprint 61301411821 (14 row, straight, gold plating)
pins: 1, 2, 3, 4, 5, 6, 7, 8, 9, 10, 11, 12, 13, 14

## WE-2.54 mm Socket Header 61301511821
designator C?
WR-PHD 2.54 mm Socket Header; Manufacturer: Würth Elektronik eiSos GmbH; ComponentLink1 Description: Manufacturer; ComponentLink2 Description: Datasheet; NoPins: 15
footprint 61301511821 (15 row, straight, gold plating)
pins: 1, 2, 3, 4, 5, 6, 7, 8, 9, 10, 11, 12, 13, 14, 15

## WE-2.54 mm Socket Header 61301611821
designator C?
WR-PHD 2.54 mm Socket Header; Manufacturer: Würth Elektronik eiSos GmbH; ComponentLink1 Description: Manufacturer; ComponentLink2 Description: Datasheet; NoPins: 16
footprint 61301611821 (16 row, straight, gold plating)
pins: 1, 2, 3, 4, 5, 6, 7, 8, 9, 10, 11, 12, 13, 14, 15, 16

## WE-2.54 mm Socket Header 61301811821
designator C?
WR-PHD 2.54 mm Socket Header; Manufacturer: Würth Elektronik eiSos GmbH; ComponentLink1 Description: Manufacturer; ComponentLink2 Description: Datasheet; NoPins: 18
footprint 61301811821 (18 row, straight, gold plating)
pins: 1, 2, 3, 4, 5, 6, 7, 8, 9, 10, 11, 12, 13, 14, 15, 16, 17, 18

## WE-2.54 mm Socket Header 61302011821
designator C?
WR-PHD 2.54 mm Socket Header; Manufacturer: Würth Elektronik eiSos GmbH; ComponentLink1 Description: Manufacturer; ComponentLink2 Description: Datasheet; NoPins: 20
footprint 61302011821 (20 row, straight, gold plating)
pins: 1, 2, 3, 4, 5, 6, 7, 8, 9, 10, 11, 12, 13, 14, 15, 16, 17, 18, 19, 20

## WE-2.54 mm Socket Header 61302211821
designator C?
WR-PHD 2.54 mm Socket Header; Manufacturer: Würth Elektronik eiSos GmbH; ComponentLink1 Description: Manufacturer; ComponentLink2 Description: Datasheet; NoPins: 22
footprint 61302211821 (22 row, straight, gold plating)
pins: 1, 2, 3, 4, 5, 6, 7, 8, 9, 10, 11, 12, 13, 14, 15, 16, 17, 18, 19, 20, 21, 22

## WE-2.54 mm Socket Header 61302411821
designator C?
WR-PHD 2.54 mm Socket Header; Manufacturer: Würth Elektronik eiSos GmbH; ComponentLink1 Description: Manufacturer; ComponentLink2 Description: Datasheet; NoPins: 24
footprint 61302411821 (24 row, straight, gold plating)
pins: 1, 2, 3, 4, 5, 6, 7, 8, 9, 10, 11, 12, 13, 14, 15, 16, 17, 18, 19, 20, 21, 22, 23, 24

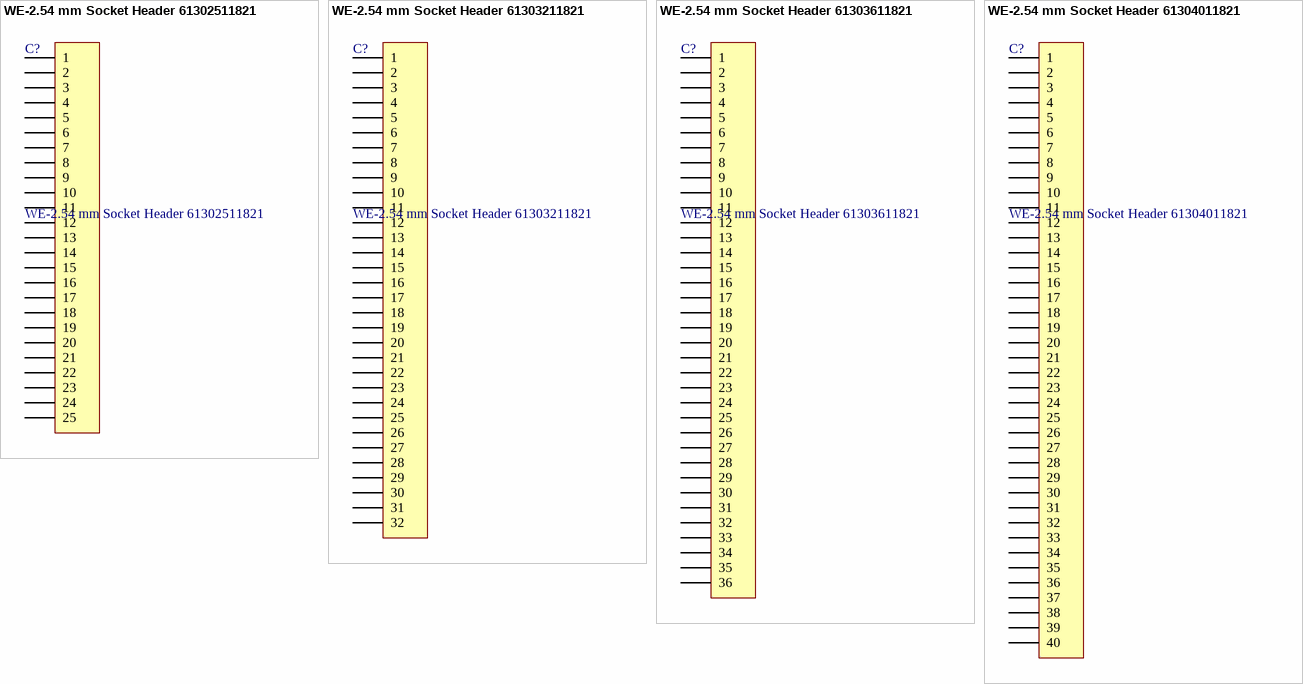
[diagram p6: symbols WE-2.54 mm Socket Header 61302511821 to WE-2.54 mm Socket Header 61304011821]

## WE-2.54 mm Socket Header 61302511821
designator C?
WR-PHD 2.54 mm Socket Header; Manufacturer: Würth Elektronik eiSos GmbH; ComponentLink1 Description: Manufacturer; ComponentLink2 Description: Datasheet; NoPins: 25
footprint 61302511821 (25 row, straight, gold plating)
pins: 1, 2, 3, 4, 5, 6, 7, 8, 9, 10, 11, 12, 13, 14, 15, 16, 17, 18, 19, 20, 21, 22, 23, 24, 25

## WE-2.54 mm Socket Header 61303211821
designator C?
WR-PHD 2.54 mm Socket Header; Manufacturer: Würth Elektronik eiSos GmbH; ComponentLink1 Description: Manufacturer; ComponentLink2 Description: Datasheet; NoPins: 32
footprint 61303211821 (32 row, straight, gold plating)
pins: 1, 2, 3, 4, 5, 6, 7, 8, 9, 10, 11, 12, 13, 14, 15, 16, 17, 18, 19, 20, 21, 22, 23, 24, 25, 26, 27, 28, 29, 30, 31, 32

## WE-2.54 mm Socket Header 61303611821
designator C?
WR-PHD 2.54 mm Socket Header; Manufacturer: Würth Elektronik eiSos GmbH; ComponentLink1 Description: Manufacturer; ComponentLink2 Description: Datasheet; NoPins: 36
footprint 61303611821 (36 row, straight, gold plating)
pins: 1, 2, 3, 4, 5, 6, 7, 8, 9, 10, 11, 12, 13, 14, 15, 16, 17, 18, 19, 20, 21, 22, 23, 24, 25, 26, 27, 28, 29, 30, 31, 32, 33, 34, 35, 36

## WE-2.54 mm Socket Header 61304011821
designator C?
WR-PHD 2.54 mm Socket Header; Manufacturer: Würth Elektronik eiSos GmbH; ComponentLink1 Description: Manufacturer; ComponentLink2 Description: Datasheet; NoPins: 40
footprint 61304011821 (40 row, straight, gold plating)
pins: 1, 2, 3, 4, 5, 6, 7, 8, 9, 10, 11, 12, 13, 14, 15, 16, 17, 18, 19, 20, 21, 22, 23, 24, 25, 26, 27, 28, 29, 30, 31, 32, 33, 34, 35, 36, 37, 38, 39, 40


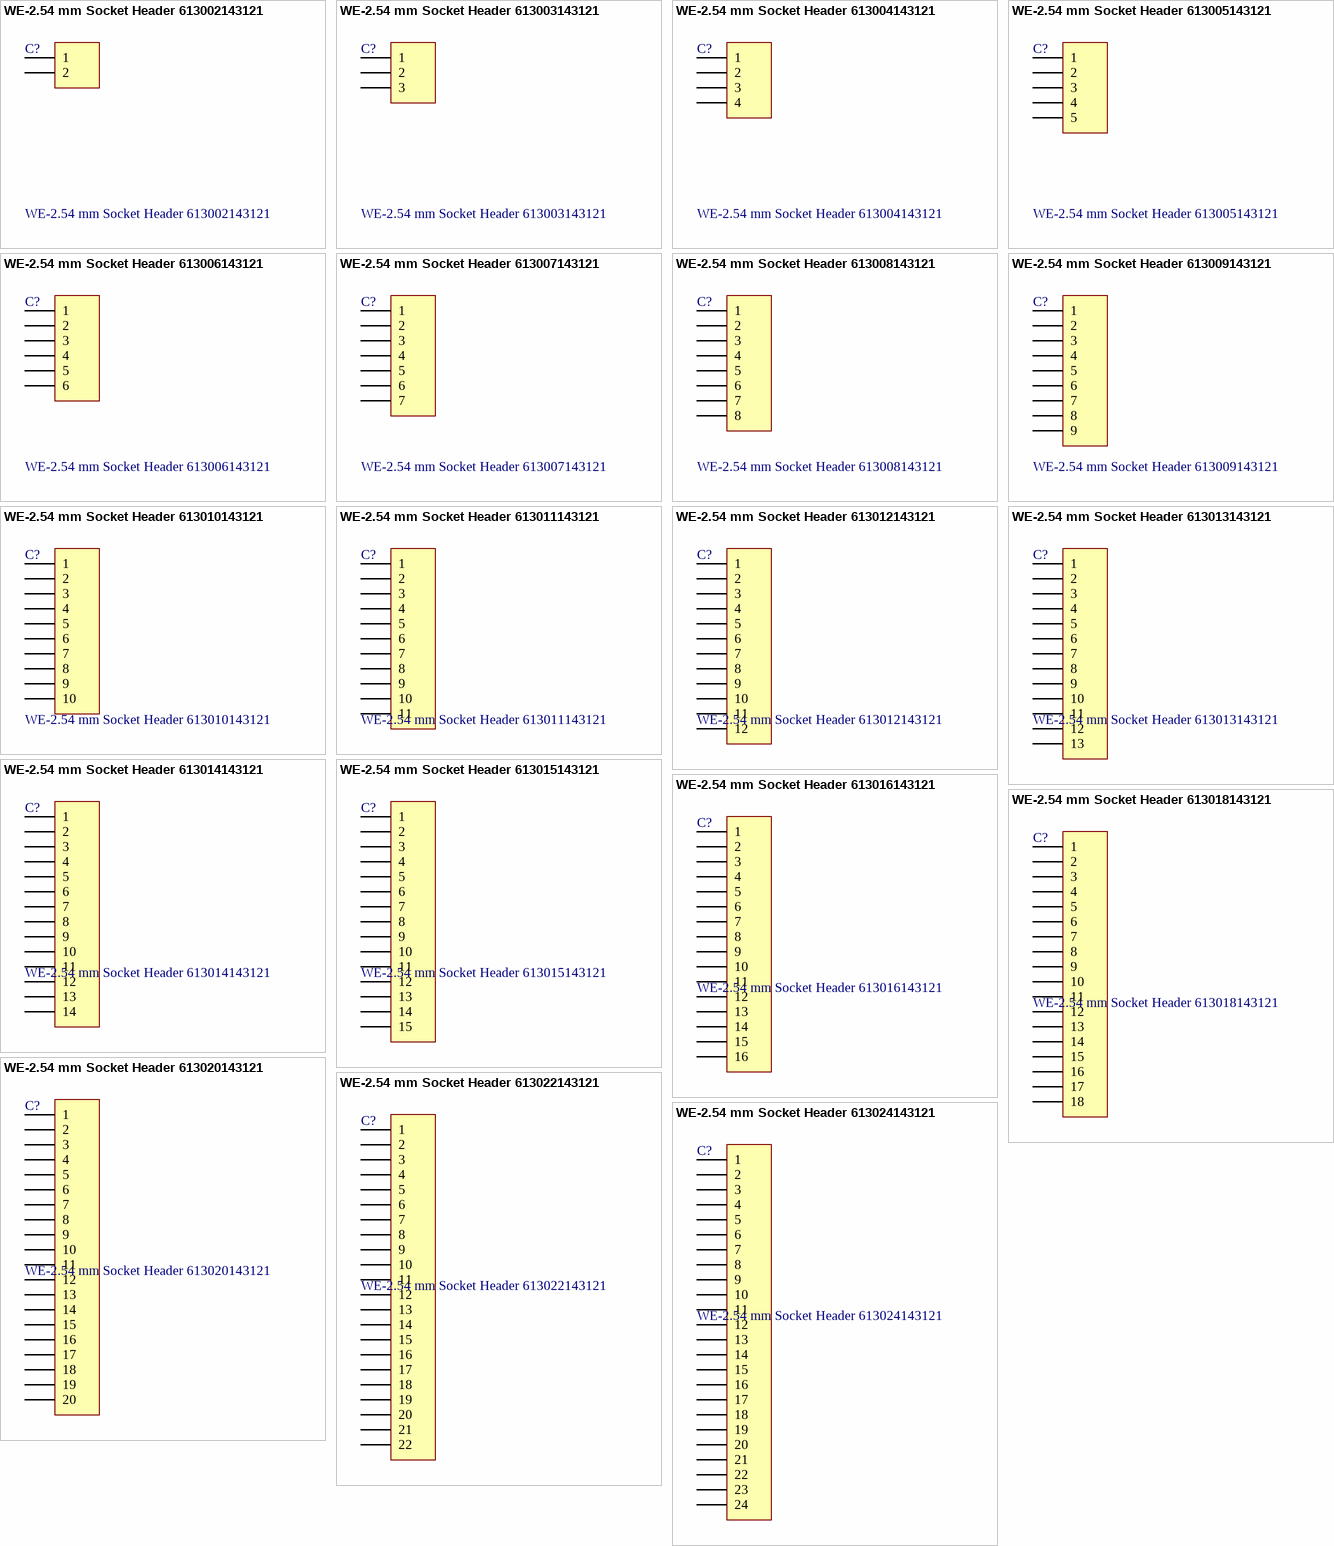
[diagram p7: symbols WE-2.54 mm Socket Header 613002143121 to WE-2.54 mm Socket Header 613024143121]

## WE-2.54 mm Socket Header 613002143121
designator C?
WR-PHD 2.54 mm Angled Socket Header; Manufacturer: Würth Elektronik eiSos GmbH; ComponentLink1 Description: Manufacturer; ComponentLink2 Description: Datasheet; NoPins: 02
footprint 613002143121 (02p 1 row Right angle)
pins: 1, 2

## WE-2.54 mm Socket Header 613003143121
designator C?
WR-PHD 2.54 mm Angled Socket Header; Manufacturer: Würth Elektronik eiSos GmbH; ComponentLink1 Description: Manufacturer; ComponentLink2 Description: Datasheet; NoPins: 03
footprint 613003143121 (03p 1 row Right angle)
pins: 1, 2, 3

## WE-2.54 mm Socket Header 613004143121
designator C?
WR-PHD 2.54 mm Angled Socket Header; Manufacturer: Würth Elektronik eiSos GmbH; ComponentLink1 Description: Manufacturer; ComponentLink2 Description: Datasheet; NoPins: 04
footprint 613004143121 (04p 1 row Right angle)
pins: 1, 2, 3, 4

## WE-2.54 mm Socket Header 613005143121
designator C?
WR-PHD 2.54 mm Angled Socket Header; Manufacturer: Würth Elektronik eiSos GmbH; ComponentLink1 Description: Manufacturer; ComponentLink2 Description: Datasheet; NoPins: 05
footprint 613005143121 (05p 1 row Right angle)
pins: 1, 2, 3, 4, 5

## WE-2.54 mm Socket Header 613006143121
designator C?
WR-PHD 2.54 mm Angled Socket Header; Manufacturer: Würth Elektronik eiSos GmbH; ComponentLink1 Description: Manufacturer; ComponentLink2 Description: Datasheet; NoPins: 06
footprint 613006143121 (06p 1 row Right angle)
pins: 1, 2, 3, 4, 5, 6

## WE-2.54 mm Socket Header 613007143121
designator C?
WR-PHD 2.54 mm Angled Socket Header; Manufacturer: Würth Elektronik eiSos GmbH; ComponentLink1 Description: Manufacturer; ComponentLink2 Description: Datasheet; NoPins: 07
footprint 613007143121 (07p 1 row Right angle)
pins: 1, 2, 3, 4, 5, 6, 7

## WE-2.54 mm Socket Header 613008143121
designator C?
WR-PHD 2.54 mm Angled Socket Header; Manufacturer: Würth Elektronik eiSos GmbH; ComponentLink1 Description: Manufacturer; ComponentLink2 Description: Datasheet; NoPins: 08
footprint 613008143121 (08p 1 row Right angle)
pins: 1, 2, 3, 4, 5, 6, 7, 8

## WE-2.54 mm Socket Header 613009143121
designator C?
WR-PHD 2.54 mm Angled Socket Header; Manufacturer: Würth Elektronik eiSos GmbH; ComponentLink1 Description: Manufacturer; ComponentLink2 Description: Datasheet; NoPins: 09
footprint 613009143121 (09p 1 row Right angle)
pins: 1, 2, 3, 4, 5, 6, 7, 8, 9

## WE-2.54 mm Socket Header 613010143121
designator C?
WR-PHD 2.54 mm Angled Socket Header; Manufacturer: Würth Elektronik eiSos GmbH; ComponentLink1 Description: Manufacturer; ComponentLink2 Description: Datasheet; NoPins: 10
footprint 613010143121 (10p 1 row Right angle)
pins: 1, 2, 3, 4, 5, 6, 7, 8, 9, 10

## WE-2.54 mm Socket Header 613011143121
designator C?
WR-PHD 2.54 mm Angled Socket Header; Manufacturer: Würth Elektronik eiSos GmbH; ComponentLink1 Description: Manufacturer; ComponentLink2 Description: Datasheet; NoPins: 11
footprint 613011143121 (11p 1 row Right angle)
pins: 1, 2, 3, 4, 5, 6, 7, 8, 9, 10, 11

## WE-2.54 mm Socket Header 613012143121
designator C?
WR-PHD 2.54 mm Angled Socket Header; Manufacturer: Würth Elektronik eiSos GmbH; ComponentLink1 Description: Manufacturer; ComponentLink2 Description: Datasheet; NoPins: 12
footprint 613012143121 (12p 1 row Right angle)
pins: 1, 2, 3, 4, 5, 6, 7, 8, 9, 10, 11, 12

## WE-2.54 mm Socket Header 613013143121
designator C?
WR-PHD 2.54 mm Angled Socket Header; Manufacturer: Würth Elektronik eiSos GmbH; ComponentLink1 Description: Manufacturer; ComponentLink2 Description: Datasheet; NoPins: 13
footprint 613013143121 (13p 1 row Right angle)
pins: 1, 2, 3, 4, 5, 6, 7, 8, 9, 10, 11, 12, 13

## WE-2.54 mm Socket Header 613014143121
designator C?
WR-PHD 2.54 mm Angled Socket Header; Manufacturer: Würth Elektronik eiSos GmbH; ComponentLink1 Description: Manufacturer; ComponentLink2 Description: Datasheet; NoPins: 14
footprint 613014143121 (14p 1 row Right angle)
pins: 1, 2, 3, 4, 5, 6, 7, 8, 9, 10, 11, 12, 13, 14

## WE-2.54 mm Socket Header 613015143121
designator C?
WR-PHD 2.54 mm Angled Socket Header; Manufacturer: Würth Elektronik eiSos GmbH; ComponentLink1 Description: Manufacturer; ComponentLink2 Description: Datasheet; NoPins: 15
footprint 613015143121 (15p 1 row Right angle)
pins: 1, 2, 3, 4, 5, 6, 7, 8, 9, 10, 11, 12, 13, 14, 15

## WE-2.54 mm Socket Header 613016143121
designator C?
WR-PHD 2.54 mm Angled Socket Header; Manufacturer: Würth Elektronik eiSos GmbH; ComponentLink1 Description: Manufacturer; ComponentLink2 Description: Datasheet; NoPins: 16
footprint 613016143121 (16p 1 row Right angle)
pins: 1, 2, 3, 4, 5, 6, 7, 8, 9, 10, 11, 12, 13, 14, 15, 16

## WE-2.54 mm Socket Header 613018143121
designator C?
WR-PHD 2.54 mm Angled Socket Header; Manufacturer: Würth Elektronik eiSos GmbH; ComponentLink1 Description: Manufacturer; ComponentLink2 Description: Datasheet; NoPins: 18
footprint 613018143121 (18p 1 row Right angle)
pins: 1, 2, 3, 4, 5, 6, 7, 8, 9, 10, 11, 12, 13, 14, 15, 16, 17, 18

## WE-2.54 mm Socket Header 613020143121
designator C?
WR-PHD 2.54 mm Angled Socket Header; Manufacturer: Würth Elektronik eiSos GmbH; ComponentLink1 Description: Manufacturer; ComponentLink2 Description: Datasheet; NoPins: 20
footprint 613020143121 (20p 1 row Right angle)
pins: 1, 2, 3, 4, 5, 6, 7, 8, 9, 10, 11, 12, 13, 14, 15, 16, 17, 18, 19, 20

## WE-2.54 mm Socket Header 613022143121
designator C?
WR-PHD 2.54 mm Angled Socket Header; Manufacturer: Würth Elektronik eiSos GmbH; ComponentLink1 Description: Manufacturer; ComponentLink2 Description: Datasheet; NoPins: 22
footprint 613022143121 (22p 1 row Right angle)
pins: 1, 2, 3, 4, 5, 6, 7, 8, 9, 10, 11, 12, 13, 14, 15, 16, 17, 18, 19, 20, 21, 22

## WE-2.54 mm Socket Header 613024143121
designator C?
WR-PHD 2.54 mm Angled Socket Header; Manufacturer: Würth Elektronik eiSos GmbH; ComponentLink1 Description: Manufacturer; ComponentLink2 Description: Datasheet; NoPins: 24
footprint 613024143121 (24p 1 row Right angle)
pins: 1, 2, 3, 4, 5, 6, 7, 8, 9, 10, 11, 12, 13, 14, 15, 16, 17, 18, 19, 20, 21, 22, 23, 24

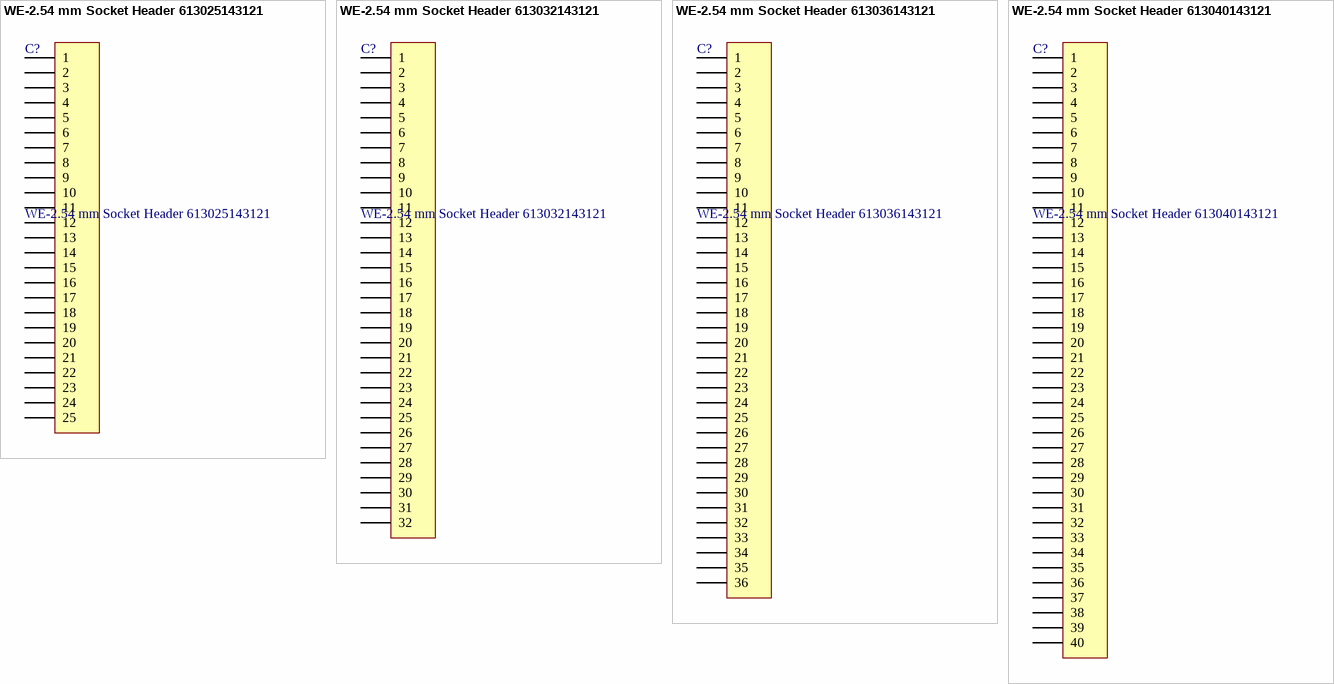
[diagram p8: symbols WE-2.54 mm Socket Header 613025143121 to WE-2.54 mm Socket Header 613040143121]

## WE-2.54 mm Socket Header 613025143121
designator C?
WR-PHD 2.54 mm Angled Socket Header; Manufacturer: Würth Elektronik eiSos GmbH; ComponentLink1 Description: Manufacturer; ComponentLink2 Description: Datasheet; NoPins: 25
footprint 613025143121 (25p 1 row Right angle)
pins: 1, 2, 3, 4, 5, 6, 7, 8, 9, 10, 11, 12, 13, 14, 15, 16, 17, 18, 19, 20, 21, 22, 23, 24, 25

## WE-2.54 mm Socket Header 613032143121
designator C?
WR-PHD 2.54 mm Angled Socket Header; Manufacturer: Würth Elektronik eiSos GmbH; ComponentLink1 Description: Manufacturer; ComponentLink2 Description: Datasheet; NoPins: 32
footprint 613032143121 (32p 1 row Right angle)
pins: 1, 2, 3, 4, 5, 6, 7, 8, 9, 10, 11, 12, 13, 14, 15, 16, 17, 18, 19, 20, 21, 22, 23, 24, 25, 26, 27, 28, 29, 30, 31, 32

## WE-2.54 mm Socket Header 613036143121
designator C?
WR-PHD 2.54 mm Angled Socket Header; Manufacturer: Würth Elektronik eiSos GmbH; ComponentLink1 Description: Manufacturer; ComponentLink2 Description: Datasheet; NoPins: 36
footprint 613036143121 (36p 1 row Right angle)
pins: 1, 2, 3, 4, 5, 6, 7, 8, 9, 10, 11, 12, 13, 14, 15, 16, 17, 18, 19, 20, 21, 22, 23, 24, 25, 26, 27, 28, 29, 30, 31, 32, 33, 34, 35, 36

## WE-2.54 mm Socket Header 613040143121
designator C?
WR-PHD 2.54 mm Angled Socket Header; Manufacturer: Würth Elektronik eiSos GmbH; ComponentLink1 Description: Manufacturer; ComponentLink2 Description: Datasheet; NoPins: 40
footprint 613040143121 (40p 1 row Right angle)
pins: 1, 2, 3, 4, 5, 6, 7, 8, 9, 10, 11, 12, 13, 14, 15, 16, 17, 18, 19, 20, 21, 22, 23, 24, 25, 26, 27, 28, 29, 30, 31, 32, 33, 34, 35, 36, 37, 38, 39, 40


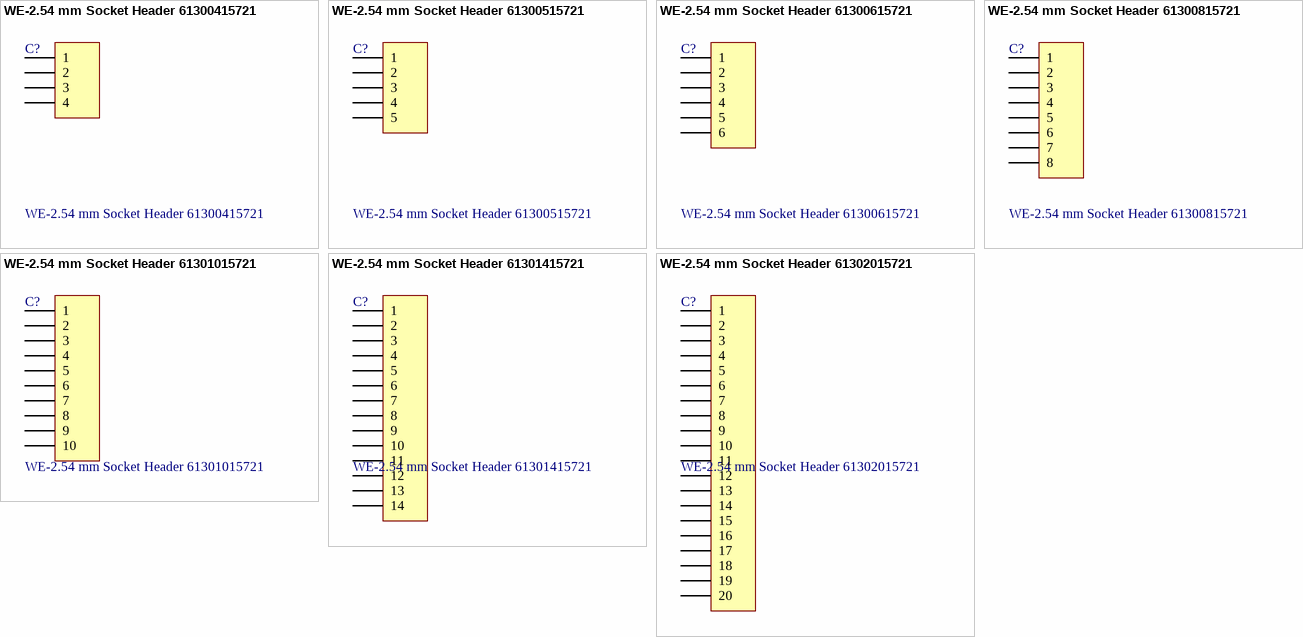
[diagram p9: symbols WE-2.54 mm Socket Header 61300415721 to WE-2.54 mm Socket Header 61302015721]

## WE-2.54 mm Socket Header 61300415721
designator C?
WR-PHD 2.54 mm Socket Header Bottom Entry; Manufacturer: Würth Elektronik eiSos GmbH; ComponentLink1 Description: Manufacturer; ComponentLink2 Description: Datasheet; NoPins: 04
footprint 61300415721 (4 pins, 1 row, straight, gold plating)
pins: 1, 2, 3, 4

## WE-2.54 mm Socket Header 61300515721
designator C?
WR-PHD 2.54 mm Socket Header Bottom Entry; Manufacturer: Würth Elektronik eiSos GmbH; ComponentLink1 Description: Manufacturer; ComponentLink2 Description: Datasheet; NoPins: 05
footprint 61300515721 (5 pins, 1 row, straight, gold plating)
pins: 1, 2, 3, 4, 5

## WE-2.54 mm Socket Header 61300615721
designator C?
WR-PHD 2.54 mm Socket Header Bottom Entry; Manufacturer: Würth Elektronik eiSos GmbH; ComponentLink1 Description: Manufacturer; ComponentLink2 Description: Datasheet; NoPins: 06
footprint 61300615721 (6 pins, 1 row, straight, gold plating)
pins: 1, 2, 3, 4, 5, 6

## WE-2.54 mm Socket Header 61300815721
designator C?
WR-PHD 2.54 mm Socket Header Bottom Entry; Manufacturer: Würth Elektronik eiSos GmbH; ComponentLink1 Description: Manufacturer; ComponentLink2 Description: Datasheet; NoPins: 08
footprint 61300815721 (8 pins, 1 row, straight, gold plating)
pins: 1, 2, 3, 4, 5, 6, 7, 8

## WE-2.54 mm Socket Header 61301015721
designator C?
WR-PHD 2.54 mm Socket Header Bottom Entry; Manufacturer: Würth Elektronik eiSos GmbH; ComponentLink1 Description: Manufacturer; ComponentLink2 Description: Datasheet; NoPins: 10
footprint 61301015721 (10 pins, 1 row, straight, gold plating)
pins: 1, 2, 3, 4, 5, 6, 7, 8, 9, 10

## WE-2.54 mm Socket Header 61301415721
designator C?
WR-PHD 2.54 mm Socket Header Bottom Entry; Manufacturer: Würth Elektronik eiSos GmbH; ComponentLink1 Description: Manufacturer; ComponentLink2 Description: Datasheet; NoPins: 14
footprint 61301415721 (14 pins, 1 row, straight, gold plating)
pins: 1, 2, 3, 4, 5, 6, 7, 8, 9, 10, 11, 12, 13, 14

## WE-2.54 mm Socket Header 61302015721
designator C?
WR-PHD 2.54 mm Socket Header Bottom Entry; Manufacturer: Würth Elektronik eiSos GmbH; ComponentLink1 Description: Manufacturer; ComponentLink2 Description: Datasheet; NoPins: 20
footprint 61302015721 (20 pins, 1 row, straight, gold plating)
pins: 1, 2, 3, 4, 5, 6, 7, 8, 9, 10, 11, 12, 13, 14, 15, 16, 17, 18, 19, 20


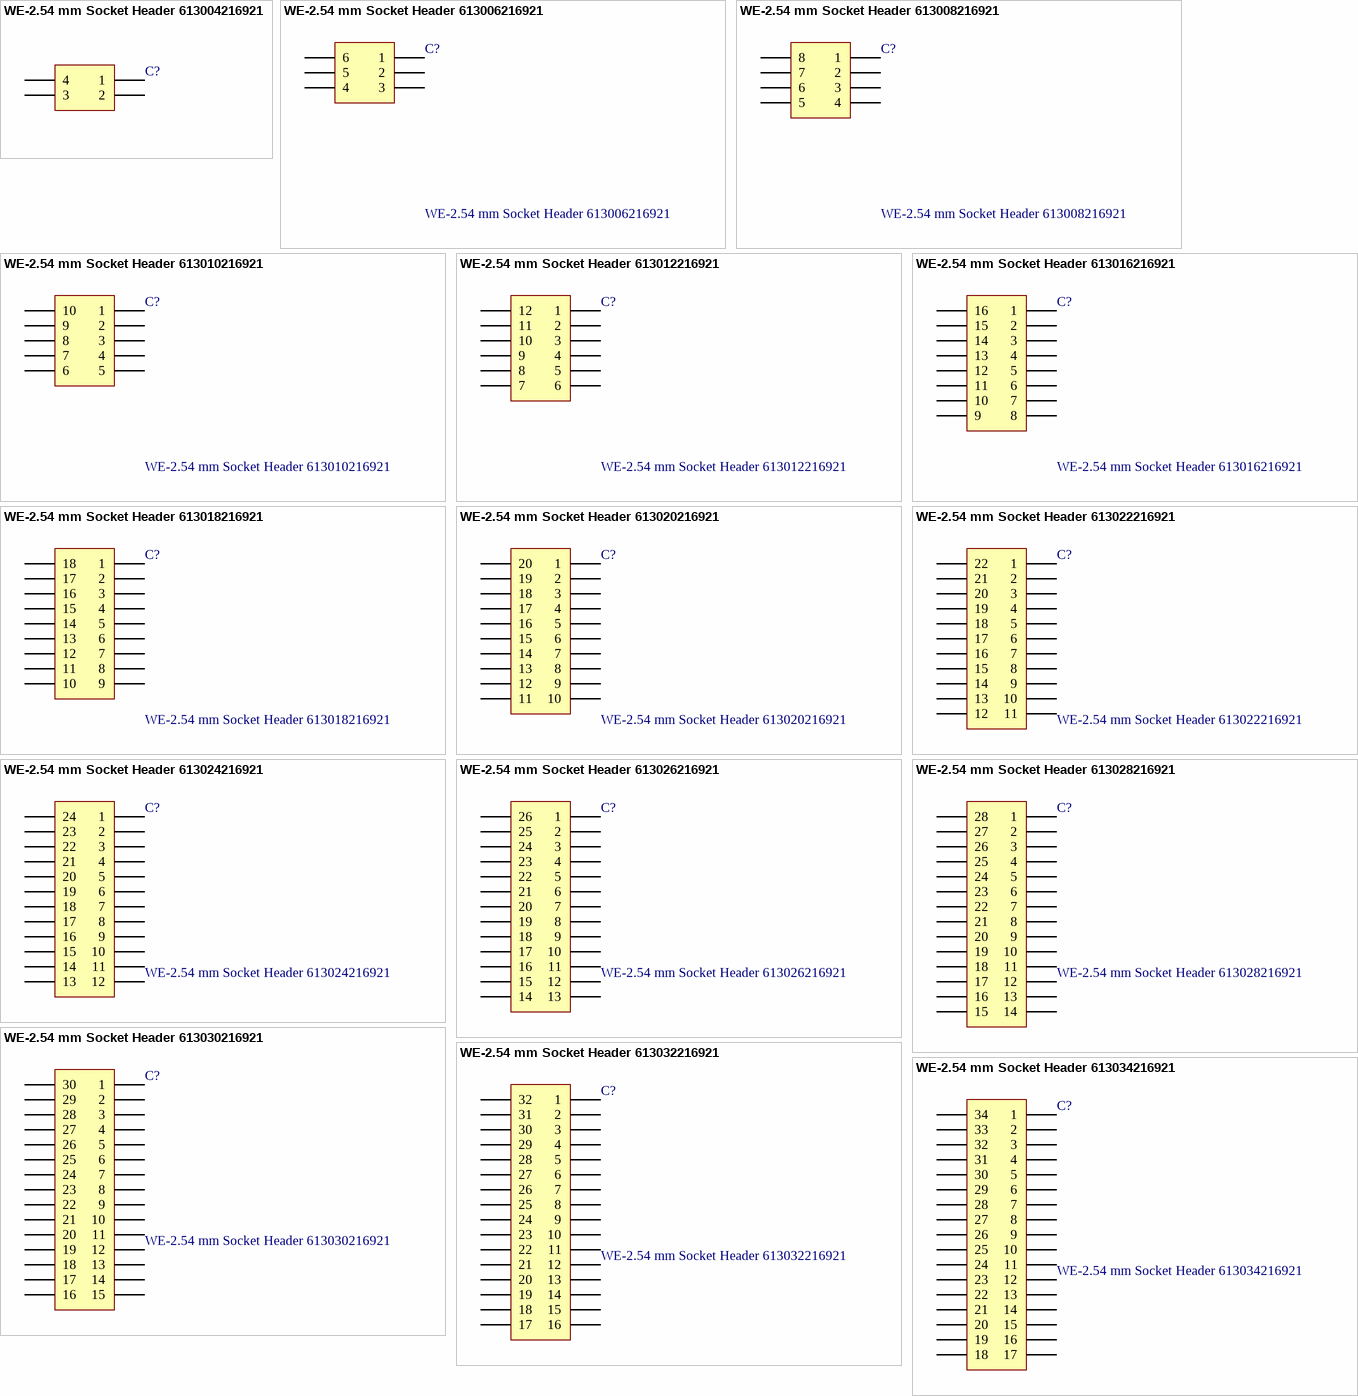
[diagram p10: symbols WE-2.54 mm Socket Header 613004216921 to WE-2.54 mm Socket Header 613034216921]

## WE-2.54 mm Socket Header 613004216921
designator C?
WR-PHD 2.54 mm Dual Socket Header Bottom Entry Large; Manufacturer: Würth Elektronik eiSos GmbH; ComponentLink1 Description: Manufacturer; ComponentLink2 Description: Datasheet; NoPins: 04
footprint 613004216921 (Large, 4 pins, dual row, straight, gold plating)
pins: 1, 2, 3, 4

## WE-2.54 mm Socket Header 613006216921
designator C?
WR-PHD 2.54 mm Dual Socket Header Bottom Entry Large; Manufacturer: Würth Elektronik eiSos GmbH; ComponentLink1 Description: Manufacturer; ComponentLink2 Description: Datasheet; NoPins: 06
footprint 613006216921 (Large, 6 pins, dual row, straight, gold plating)
pins: 1, 2, 3, 4, 5, 6

## WE-2.54 mm Socket Header 613008216921
designator C?
WR-PHD 2.54 mm Dual Socket Header Bottom Entry Large; Manufacturer: Würth Elektronik eiSos GmbH; ComponentLink1 Description: Manufacturer; ComponentLink2 Description: Datasheet; NoPins: 08
footprint 613008216921 (Large, 8 pins, dual row, straight, gold plating)
pins: 1, 2, 3, 4, 5, 6, 7, 8

## WE-2.54 mm Socket Header 613010216921
designator C?
WR-PHD 2.54 mm Dual Socket Header Bottom Entry Large; Manufacturer: Würth Elektronik eiSos GmbH; ComponentLink1 Description: Manufacturer; ComponentLink2 Description: Datasheet; NoPins: 10
footprint 613010216921 (Large, 10 pins, dual row, straight, gold plating)
pins: 1, 2, 3, 4, 5, 6, 7, 8, 9, 10

## WE-2.54 mm Socket Header 613012216921
designator C?
WR-PHD 2.54 mm Dual Socket Header Bottom Entry Large; Manufacturer: Würth Elektronik eiSos GmbH; ComponentLink1 Description: Manufacturer; ComponentLink2 Description: Datasheet; NoPins: 12
footprint 613012216921 (Large, 12 pins, dual row, straight, gold plating)
pins: 1, 2, 3, 4, 5, 6, 7, 8, 9, 10, 11, 12

## WE-2.54 mm Socket Header 613016216921
designator C?
WR-PHD 2.54 mm Dual Socket Header Bottom Entry Large; Manufacturer: Würth Elektronik eiSos GmbH; ComponentLink1 Description: Manufacturer; ComponentLink2 Description: Datasheet; NoPins: 16
footprint 613016216921 (Large, 16 pins, dual row, straight, gold plating)
pins: 1, 2, 3, 4, 5, 6, 7, 8, 9, 10, 11, 12, 13, 14, 15, 16

## WE-2.54 mm Socket Header 613018216921
designator C?
WR-PHD 2.54 mm Dual Socket Header Bottom Entry Large; Manufacturer: Würth Elektronik eiSos GmbH; ComponentLink1 Description: Manufacturer; ComponentLink2 Description: Datasheet; NoPins: 18
footprint 613018216921 (Large, 18 pins, dual row, straight, gold plating)
pins: 1, 2, 3, 4, 5, 6, 7, 8, 9, 10, 11, 12, 13, 14, 15, 16, 17, 18

## WE-2.54 mm Socket Header 613020216921
designator C?
WR-PHD 2.54 mm Dual Socket Header Bottom Entry Large; Manufacturer: Würth Elektronik eiSos GmbH; ComponentLink1 Description: Manufacturer; ComponentLink2 Description: Datasheet; NoPins: 20
footprint 613020216921 (Large, 20 pins, dual row, straight, gold plating)
pins: 1, 2, 3, 4, 5, 6, 7, 8, 9, 10, 11, 12, 13, 14, 15, 16, 17, 18, 19, 20

## WE-2.54 mm Socket Header 613022216921
designator C?
WR-PHD 2.54 mm Dual Socket Header Bottom Entry Large; Manufacturer: Würth Elektronik eiSos GmbH; ComponentLink1 Description: Manufacturer; ComponentLink2 Description: Datasheet; NoPins: 22
footprint 613022216921 (Large, 22 pins, dual row, straight, gold plating)
pins: 1, 2, 3, 4, 5, 6, 7, 8, 9, 10, 11, 12, 13, 14, 15, 16, 17, 18, 19, 20, 21, 22

## WE-2.54 mm Socket Header 613024216921
designator C?
WR-PHD 2.54 mm Dual Socket Header Bottom Entry Large; Manufacturer: Würth Elektronik eiSos GmbH; ComponentLink1 Description: Manufacturer; ComponentLink2 Description: Datasheet; NoPins: 24
footprint 613024216921 (Large, 24 pins, dual row, straight, gold plating)
pins: 1, 2, 3, 4, 5, 6, 7, 8, 9, 10, 11, 12, 13, 14, 15, 16, 17, 18, 19, 20, 21, 22, 23, 24

## WE-2.54 mm Socket Header 613026216921
designator C?
WR-PHD 2.54 mm Dual Socket Header Bottom Entry Large; Manufacturer: Würth Elektronik eiSos GmbH; ComponentLink1 Description: Manufacturer; ComponentLink2 Description: Datasheet; NoPins: 26
footprint 613026216921 (Large,26 pins, dual row, straight, gold plating)
pins: 1, 2, 3, 4, 5, 6, 7, 8, 9, 10, 11, 12, 13, 14, 15, 16, 17, 18, 19, 20, 21, 22, 23, 24, 25, 26

## WE-2.54 mm Socket Header 613028216921
designator C?
WR-PHD 2.54 mm Dual Socket Header Bottom Entry Large; Manufacturer: Würth Elektronik eiSos GmbH; ComponentLink1 Description: Manufacturer; ComponentLink2 Description: Datasheet; NoPins: 28
footprint 613028216921 (Large, 28 pins, dual row, straight, gold plating)
pins: 1, 2, 3, 4, 5, 6, 7, 8, 9, 10, 11, 12, 13, 14, 15, 16, 17, 18, 19, 20, 21, 22, 23, 24, 25, 26, 27, 28

## WE-2.54 mm Socket Header 613030216921
designator C?
WR-PHD 2.54 mm Dual Socket Header Bottom Entry Large; Manufacturer: Würth Elektronik eiSos GmH; ComponentLink1 Description: Manufacturer; ComponentLink2 Description: Datasheet; NoPins: 30
footprint 613030216921 (Large, 30 pins, dual row, straight, gold plating)
pins: 1, 2, 3, 4, 5, 6, 7, 8, 9, 10, 11, 12, 13, 14, 15, 16, 17, 18, 19, 20, 21, 22, 23, 24, 25, 26, 27, 28, 29, 30

## WE-2.54 mm Socket Header 613032216921
designator C?
WR-PHD 2.54 mm Dual Socket Header Bottom Entry Large; Manufacturer: Würth Elektronik eiSos GmbH; ComponentLink1 Description: Manufacturer; ComponentLink2 Description: Datasheet; NoPins: 32
footprint 613032216921 (Large, 32 pins, dual row, straight, gold plating)
pins: 1, 2, 3, 4, 5, 6, 7, 8, 9, 10, 11, 12, 13, 14, 15, 16, 17, 18, 19, 20, 21, 22, 23, 24, 25, 26, 27, 28, 29, 30, 31, 32

## WE-2.54 mm Socket Header 613034216921
designator C?
WR-PHD 2.54 mm Dual Socket Header Bottom Entry Large; Manufacturer: Würth Elektronik eiSos GmbH; ComponentLink1 Description: Manufacturer; ComponentLink2 Description: Datasheet; NoPins: 34
footprint 613034216921 (Large, 34 pins, dual row, straight, gold plating)
pins: 1, 2, 3, 4, 5, 6, 7, 8, 9, 10, 11, 12, 13, 14, 15, 16, 17, 18, 19, 20, 21, 22, 23, 24, 25, 26, 27, 28, 29, 30, 31, 32, 33, 34

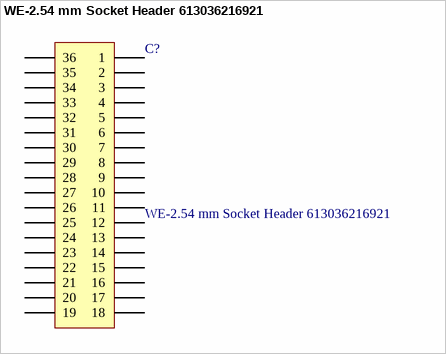
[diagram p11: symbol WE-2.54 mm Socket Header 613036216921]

## WE-2.54 mm Socket Header 613036216921
designator C?
WR-PHD 2.54 mm Dual Socket Header Bottom Entry Large; Manufacturer: Würth Elektronik eiSos GmbH; ComponentLink1 Description: Manufacturer; ComponentLink2 Description: Datasheet; NoPins: 36
footprint 613036216921 (Large, 36 pins, dual row, straight, gold plating)
pins: 1, 2, 3, 4, 5, 6, 7, 8, 9, 10, 11, 12, 13, 14, 15, 16, 17, 18, 19, 20, 21, 22, 23, 24, 25, 26, 27, 28, 29, 30, 31, 32, 33, 34, 35, 36


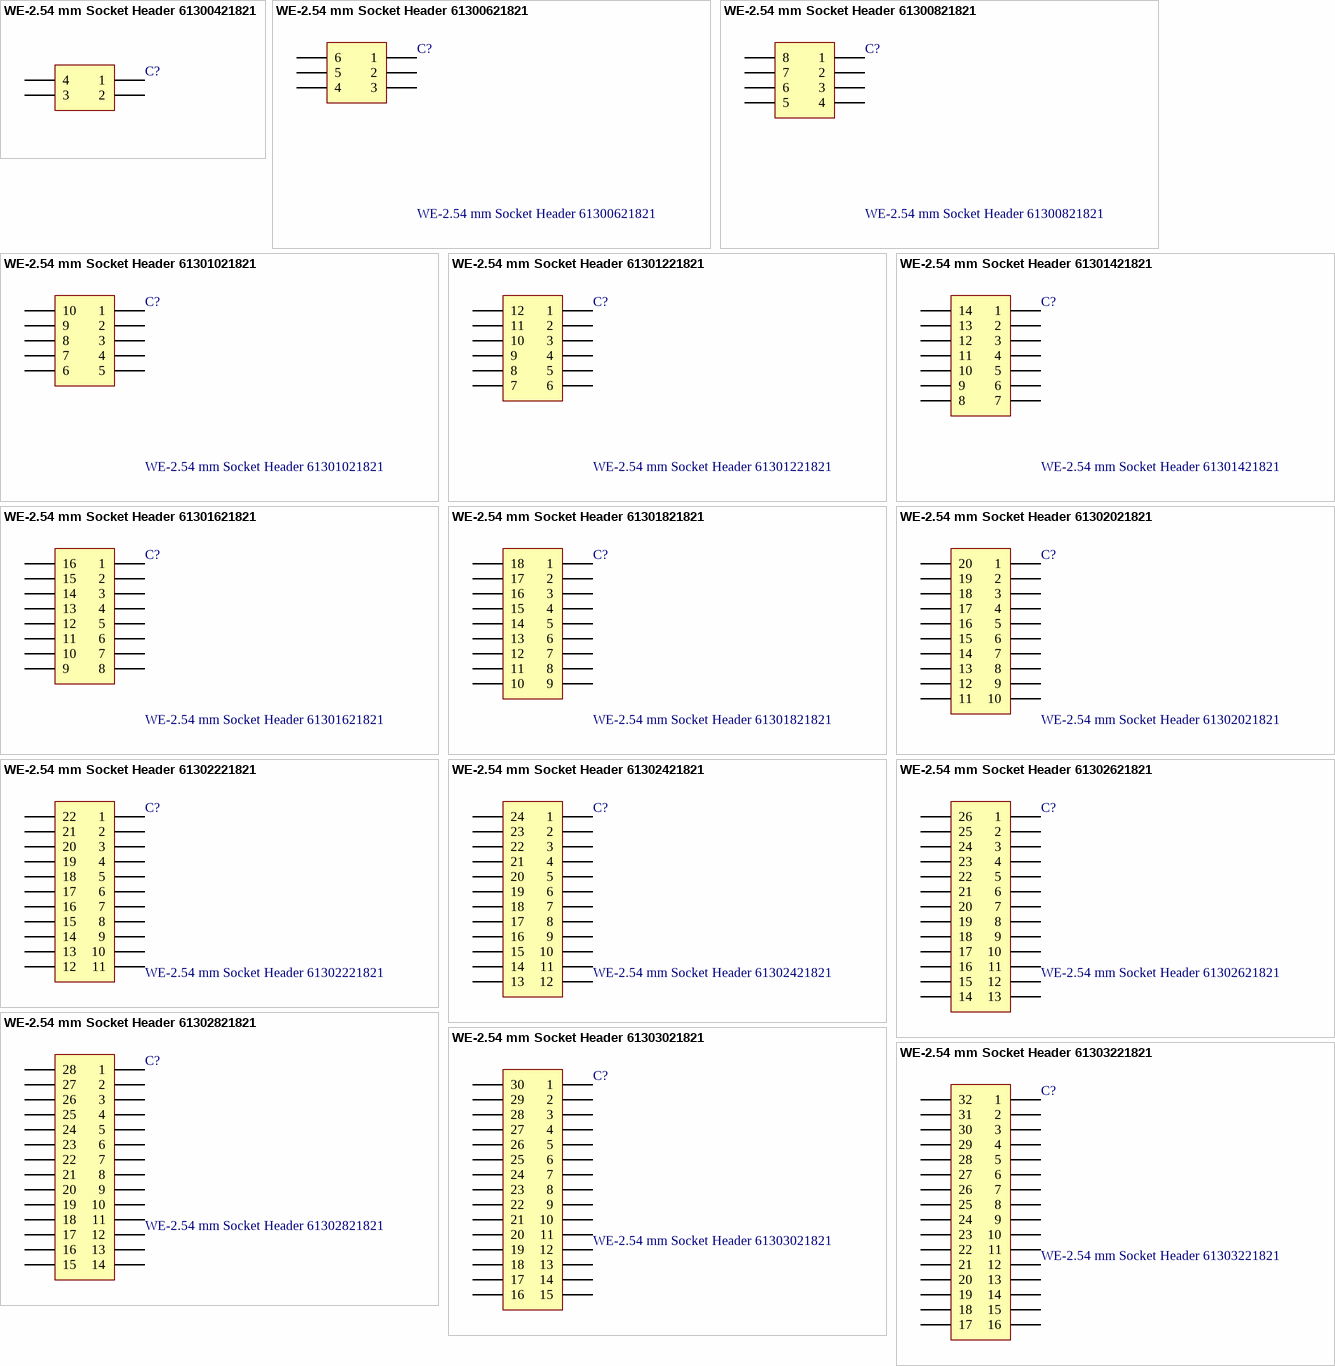
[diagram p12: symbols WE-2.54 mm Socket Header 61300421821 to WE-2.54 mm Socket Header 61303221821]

## WE-2.54 mm Socket Header 61300421821
designator C?
WR-PHD 2.54 mm Dual Socket Header; Manufacturer: Würth Elektronik eiSos GmbH; ComponentLink1 Description: Manufacturer; ComponentLink2 Description: Datasheet; NoPins: 04
footprint 61300421821 (4 pins, dual row, straight, gold plating)
pins: 1, 2, 3, 4

## WE-2.54 mm Socket Header 61300621821
designator C?
WR-PHD 2.54 mm Dual Socket Header; Manufacturer: Würth Elektronik eiSos GmbH; ComponentLink1 Description: Manufacturer; ComponentLink2 Description: Datasheet; NoPins: 06
footprint 61300621821 (6 pins, dual row, straight, gold plating)
pins: 1, 2, 3, 4, 5, 6

## WE-2.54 mm Socket Header 61300821821
designator C?
WR-PHD 2.54 mm Dual Socket Header; Manufacturer: Würth Elektronik eiSos GmbH; ComponentLink1 Description: Manufacturer; ComponentLink2 Description: Datasheet; NoPins: 08
footprint 61300821821 (8 pins, dual row, straight, gold plating)
pins: 1, 2, 3, 4, 5, 6, 7, 8

## WE-2.54 mm Socket Header 61301021821
designator C?
WR-PHD 2.54 mm Dual Socket Header; Manufacturer: Würth Elektronik eiSos GmbH; ComponentLink1 Description: Manufacturer; ComponentLink2 Description: Datasheet; NoPins: 10
footprint 61301021821 (10 pins, dual row, straight, gold plating)
pins: 1, 2, 3, 4, 5, 6, 7, 8, 9, 10

## WE-2.54 mm Socket Header 61301221821
designator C?
WR-PHD 2.54 mm Dual Socket Header; Manufacturer: Würth Elektronik eiSos GmbH; ComponentLink1 Description: Manufacturer; ComponentLink2 Description: Datasheet; NoPins: 12
footprint 61301221821 (12 pins, dual row, straight, gold plating)
pins: 1, 2, 3, 4, 5, 6, 7, 8, 9, 10, 11, 12

## WE-2.54 mm Socket Header 61301421821
designator C?
WR-PHD 2.54 mm Dual Socket Header; Manufacturer: Würth Elektronik eiSos GmbH; ComponentLink1 Description: Manufacturer; ComponentLink2 Description: Datasheet; NoPins: 14
footprint 61301421821 (14 pins, dual row, straight, gold plating)
pins: 1, 2, 3, 4, 5, 6, 7, 8, 9, 10, 11, 12, 13, 14

## WE-2.54 mm Socket Header 61301621821
designator C?
WR-PHD 2.54 mm Dual Socket Header; Manufacturer: Würth Elektronik eiSos GmbH; ComponentLink1 Description: Manufacturer; ComponentLink2 Description: Datasheet; NoPins: 16
footprint 61301621821 (16 pins, dual row, straight, gold plating)
pins: 1, 2, 3, 4, 5, 6, 7, 8, 9, 10, 11, 12, 13, 14, 15, 16

## WE-2.54 mm Socket Header 61301821821
designator C?
WR-PHD 2.54 mm Dual Socket Header; Manufacturer: Würth Elektronik eiSos GmbH; ComponentLink1 Description: Manufacturer; ComponentLink2 Description: Datasheet; NoPins: 18
footprint 61301821821 (18 pins, dual row, straight, gold plating)
pins: 1, 2, 3, 4, 5, 6, 7, 8, 9, 10, 11, 12, 13, 14, 15, 16, 17, 18

## WE-2.54 mm Socket Header 61302021821
designator C?
WR-PHD 2.54 mm Dual Socket Header; Manufacturer: Würth Elektronik eiSos GmbH; ComponentLink1 Description: Manufacturer; ComponentLink2 Description: Datasheet; NoPins: 20
footprint 61302021821 (20 pins, dual row, straight, gold plating)
pins: 1, 2, 3, 4, 5, 6, 7, 8, 9, 10, 11, 12, 13, 14, 15, 16, 17, 18, 19, 20

## WE-2.54 mm Socket Header 61302221821
designator C?
WR-PHD 2.54 mm Dual Socket Header; Manufacturer: Würth Elektronik eiSos GmbH; ComponentLink1 Description: Manufacturer; ComponentLink2 Description: Datasheet; NoPins: 22
footprint 61302221821 (22 pins, dual row, straight, gold plating)
pins: 1, 2, 3, 4, 5, 6, 7, 8, 9, 10, 11, 12, 13, 14, 15, 16, 17, 18, 19, 20, 21, 22

## WE-2.54 mm Socket Header 61302421821
designator C?
WR-PHD 2.54 mm Dual Socket Header; Manufacturer: Würth Elektronik eiSos GmbH; ComponentLink1 Description: Manufacturer; ComponentLink2 Description: Datasheet; NoPins: 24
footprint 61302421821 (24 pins, dual row, straight, gold plating)
pins: 1, 2, 3, 4, 5, 6, 7, 8, 9, 10, 11, 12, 13, 14, 15, 16, 17, 18, 19, 20, 21, 22, 23, 24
